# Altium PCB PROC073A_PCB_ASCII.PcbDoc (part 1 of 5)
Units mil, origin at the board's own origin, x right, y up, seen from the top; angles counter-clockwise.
Board outline 2165.35 x 2165.35 mil, 6 copper layers (Top Layer, L2, L3, L4, L5, Bottom Layer), stack 55.08 mil thick; 285 components, 233 nets, 945 pads, 1419 vias.
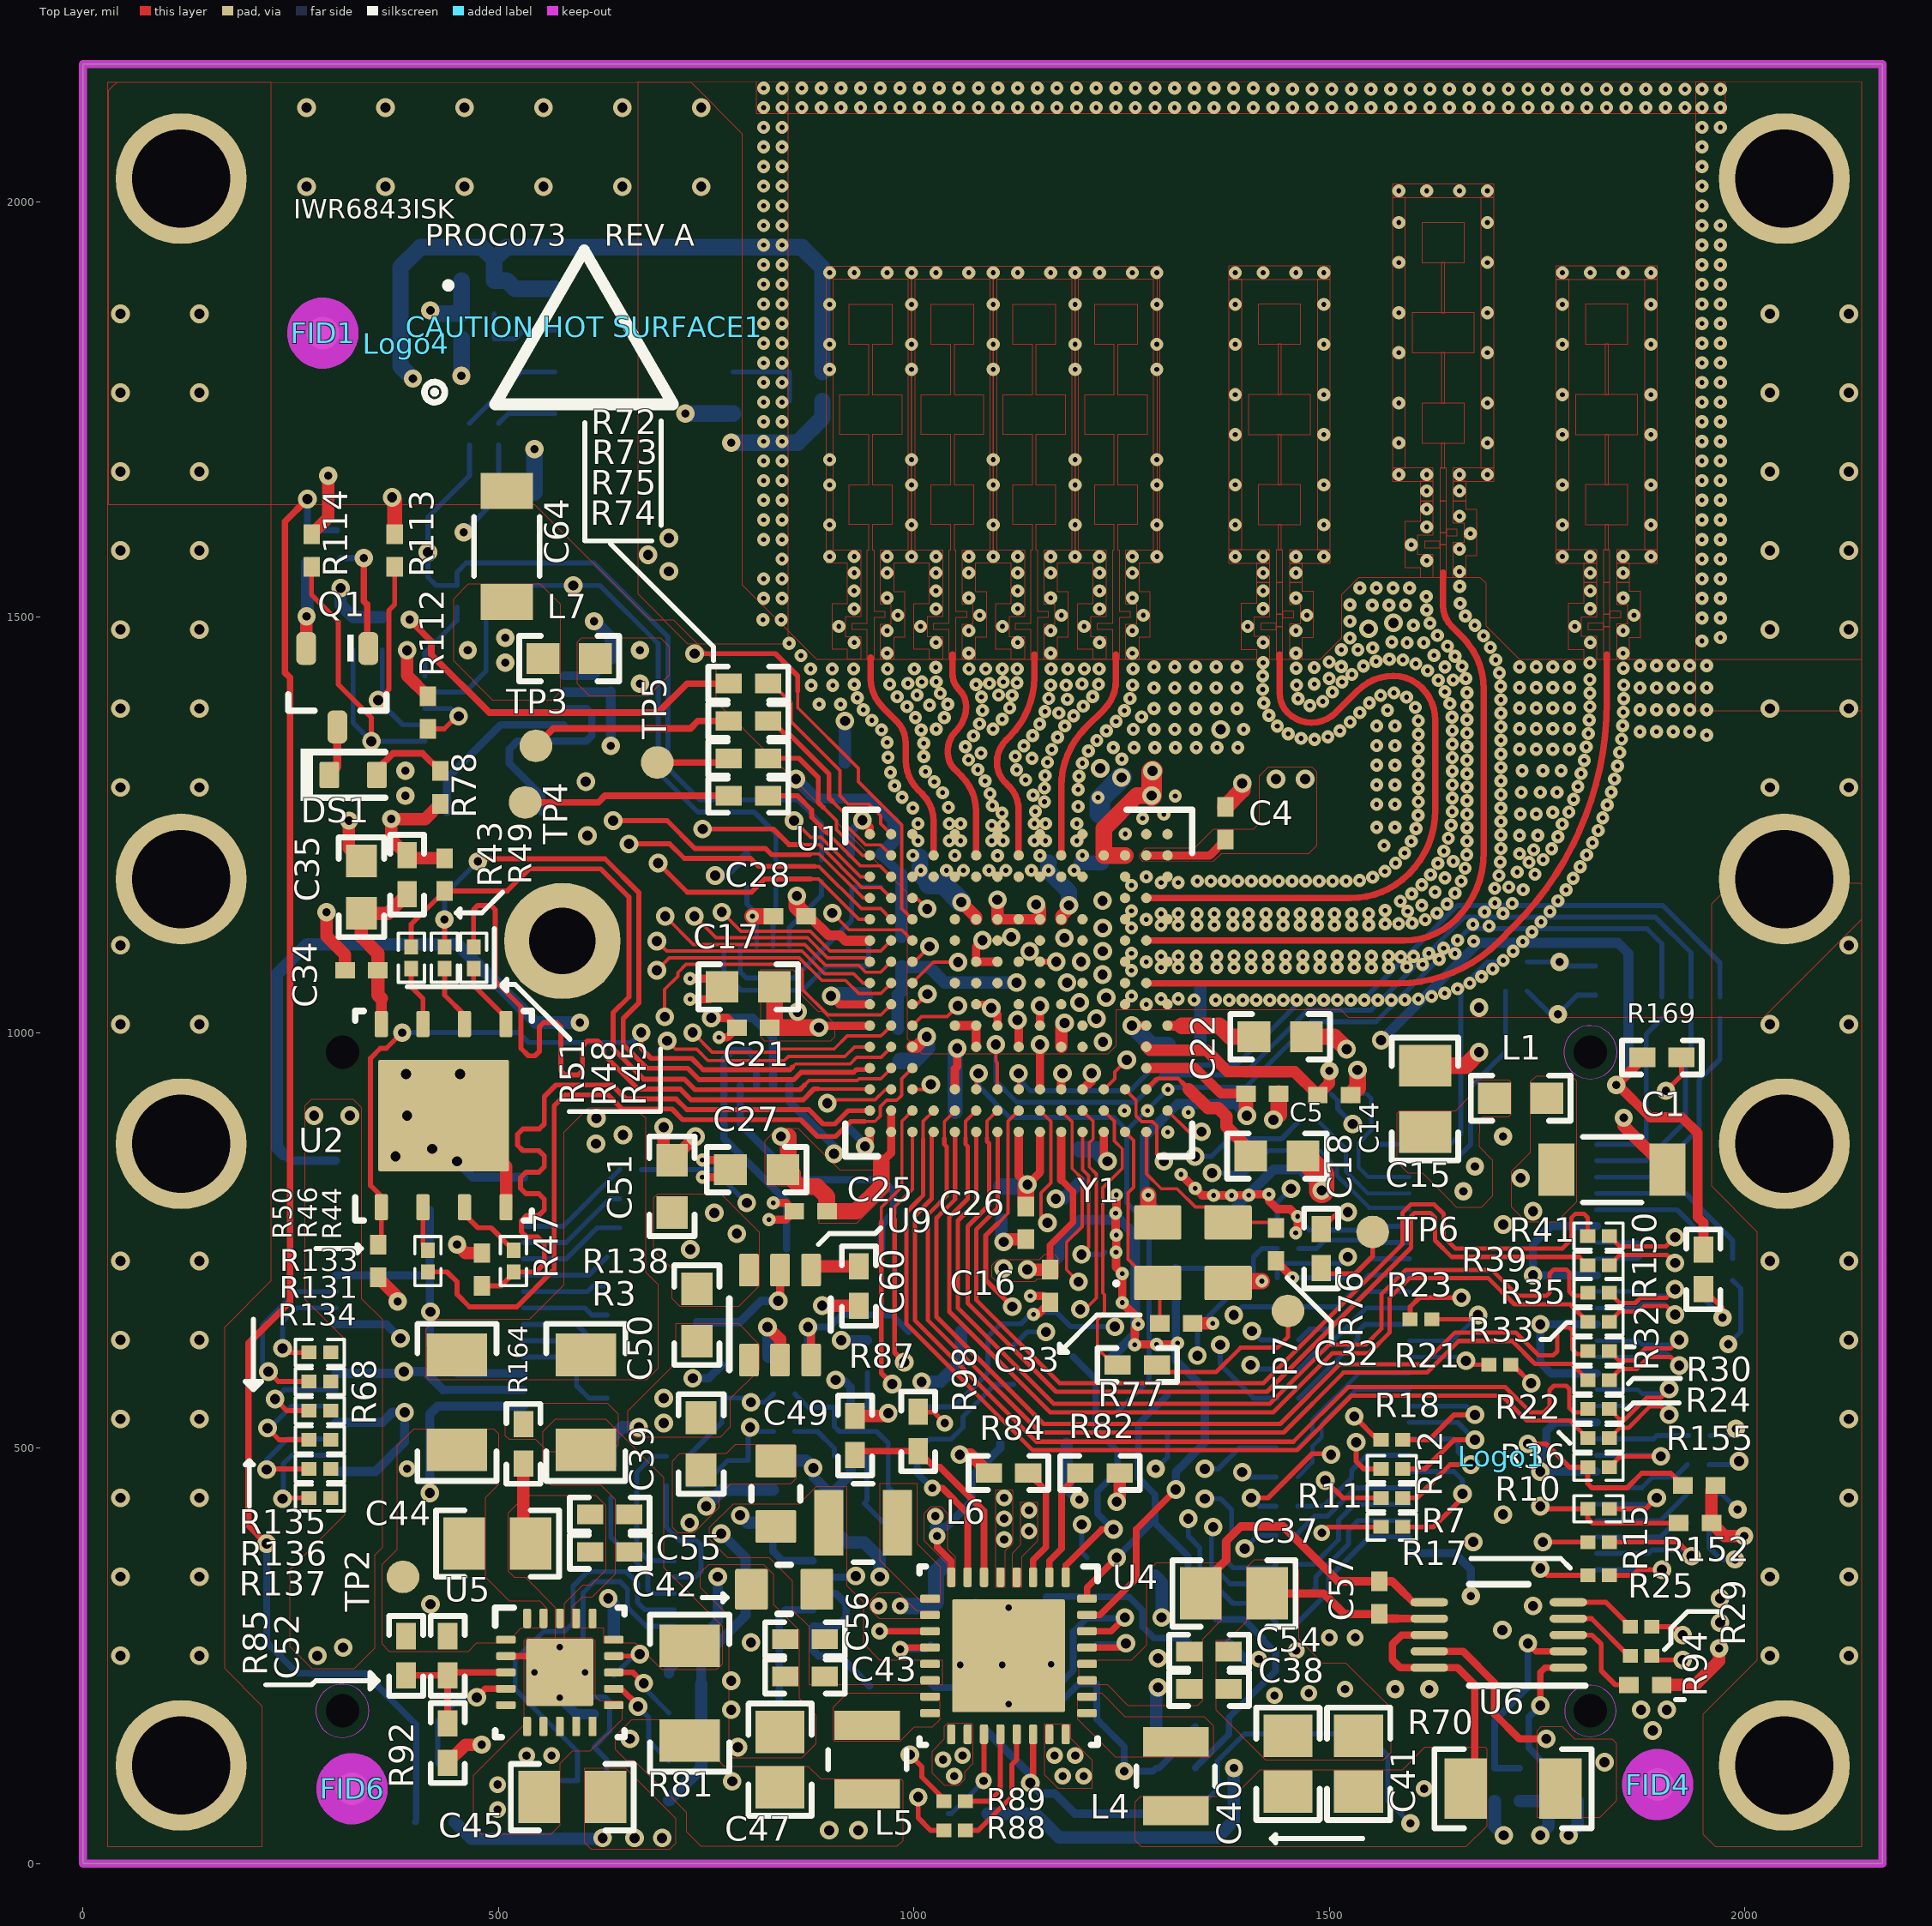
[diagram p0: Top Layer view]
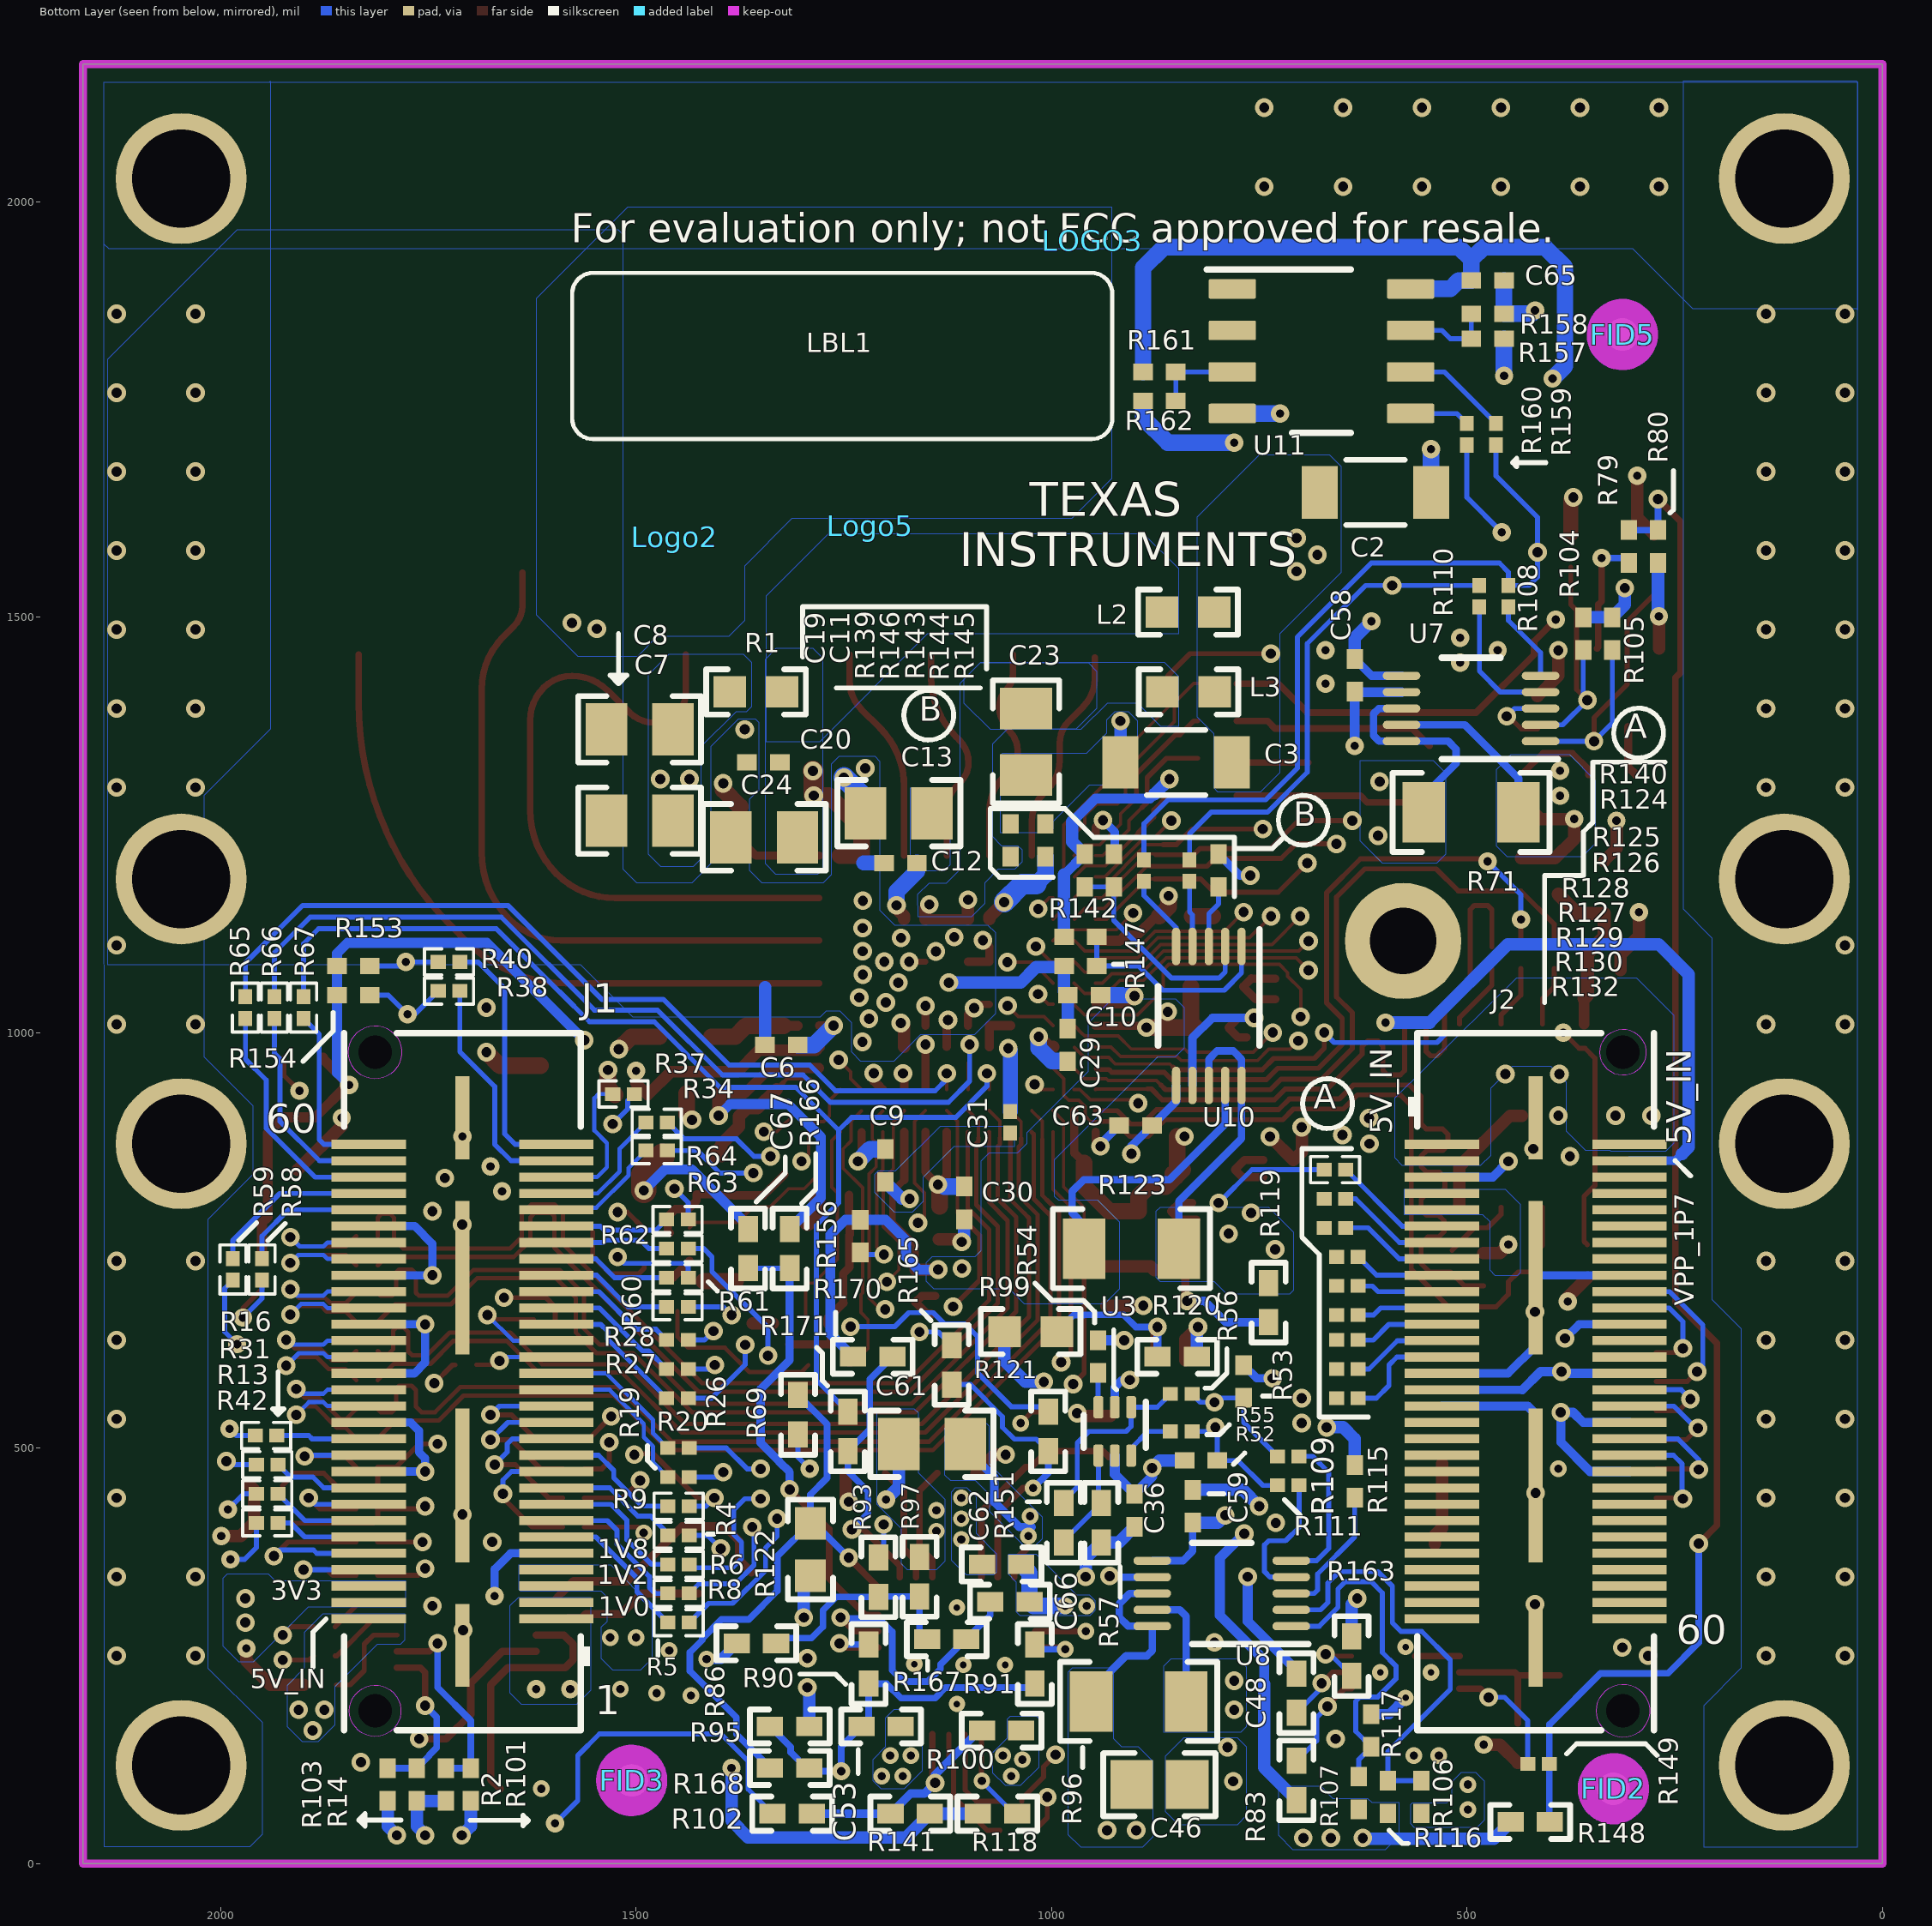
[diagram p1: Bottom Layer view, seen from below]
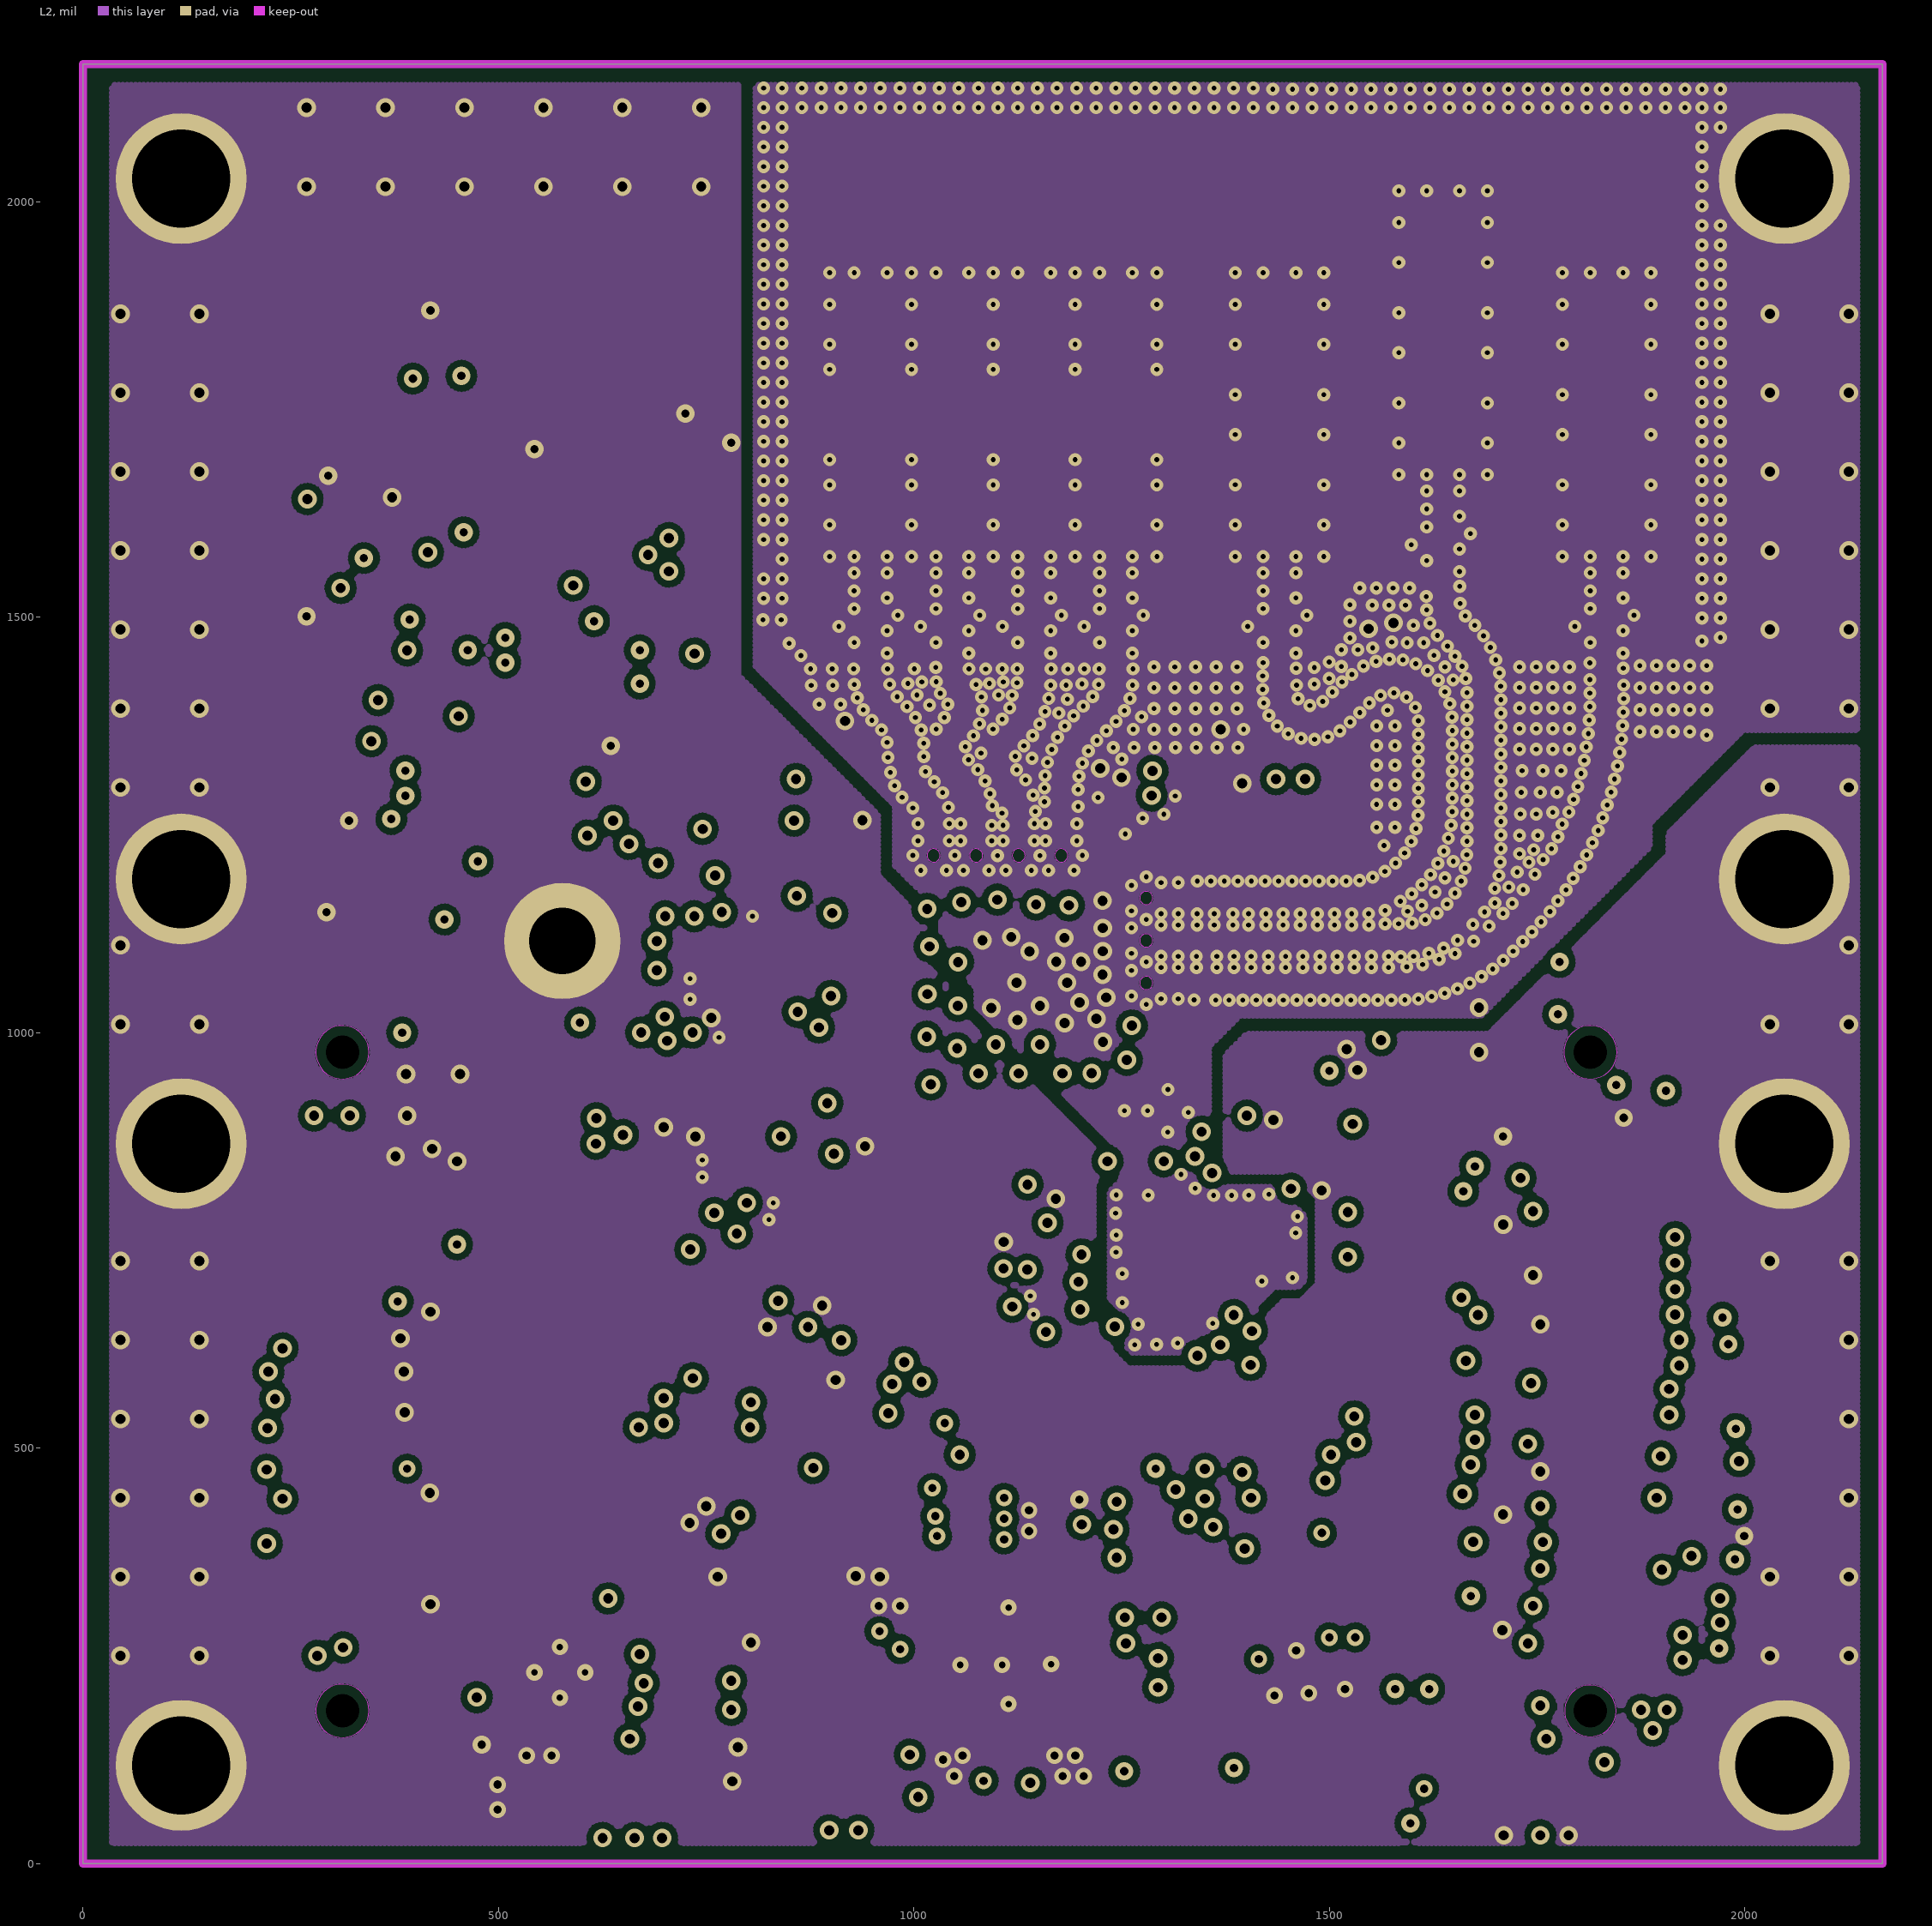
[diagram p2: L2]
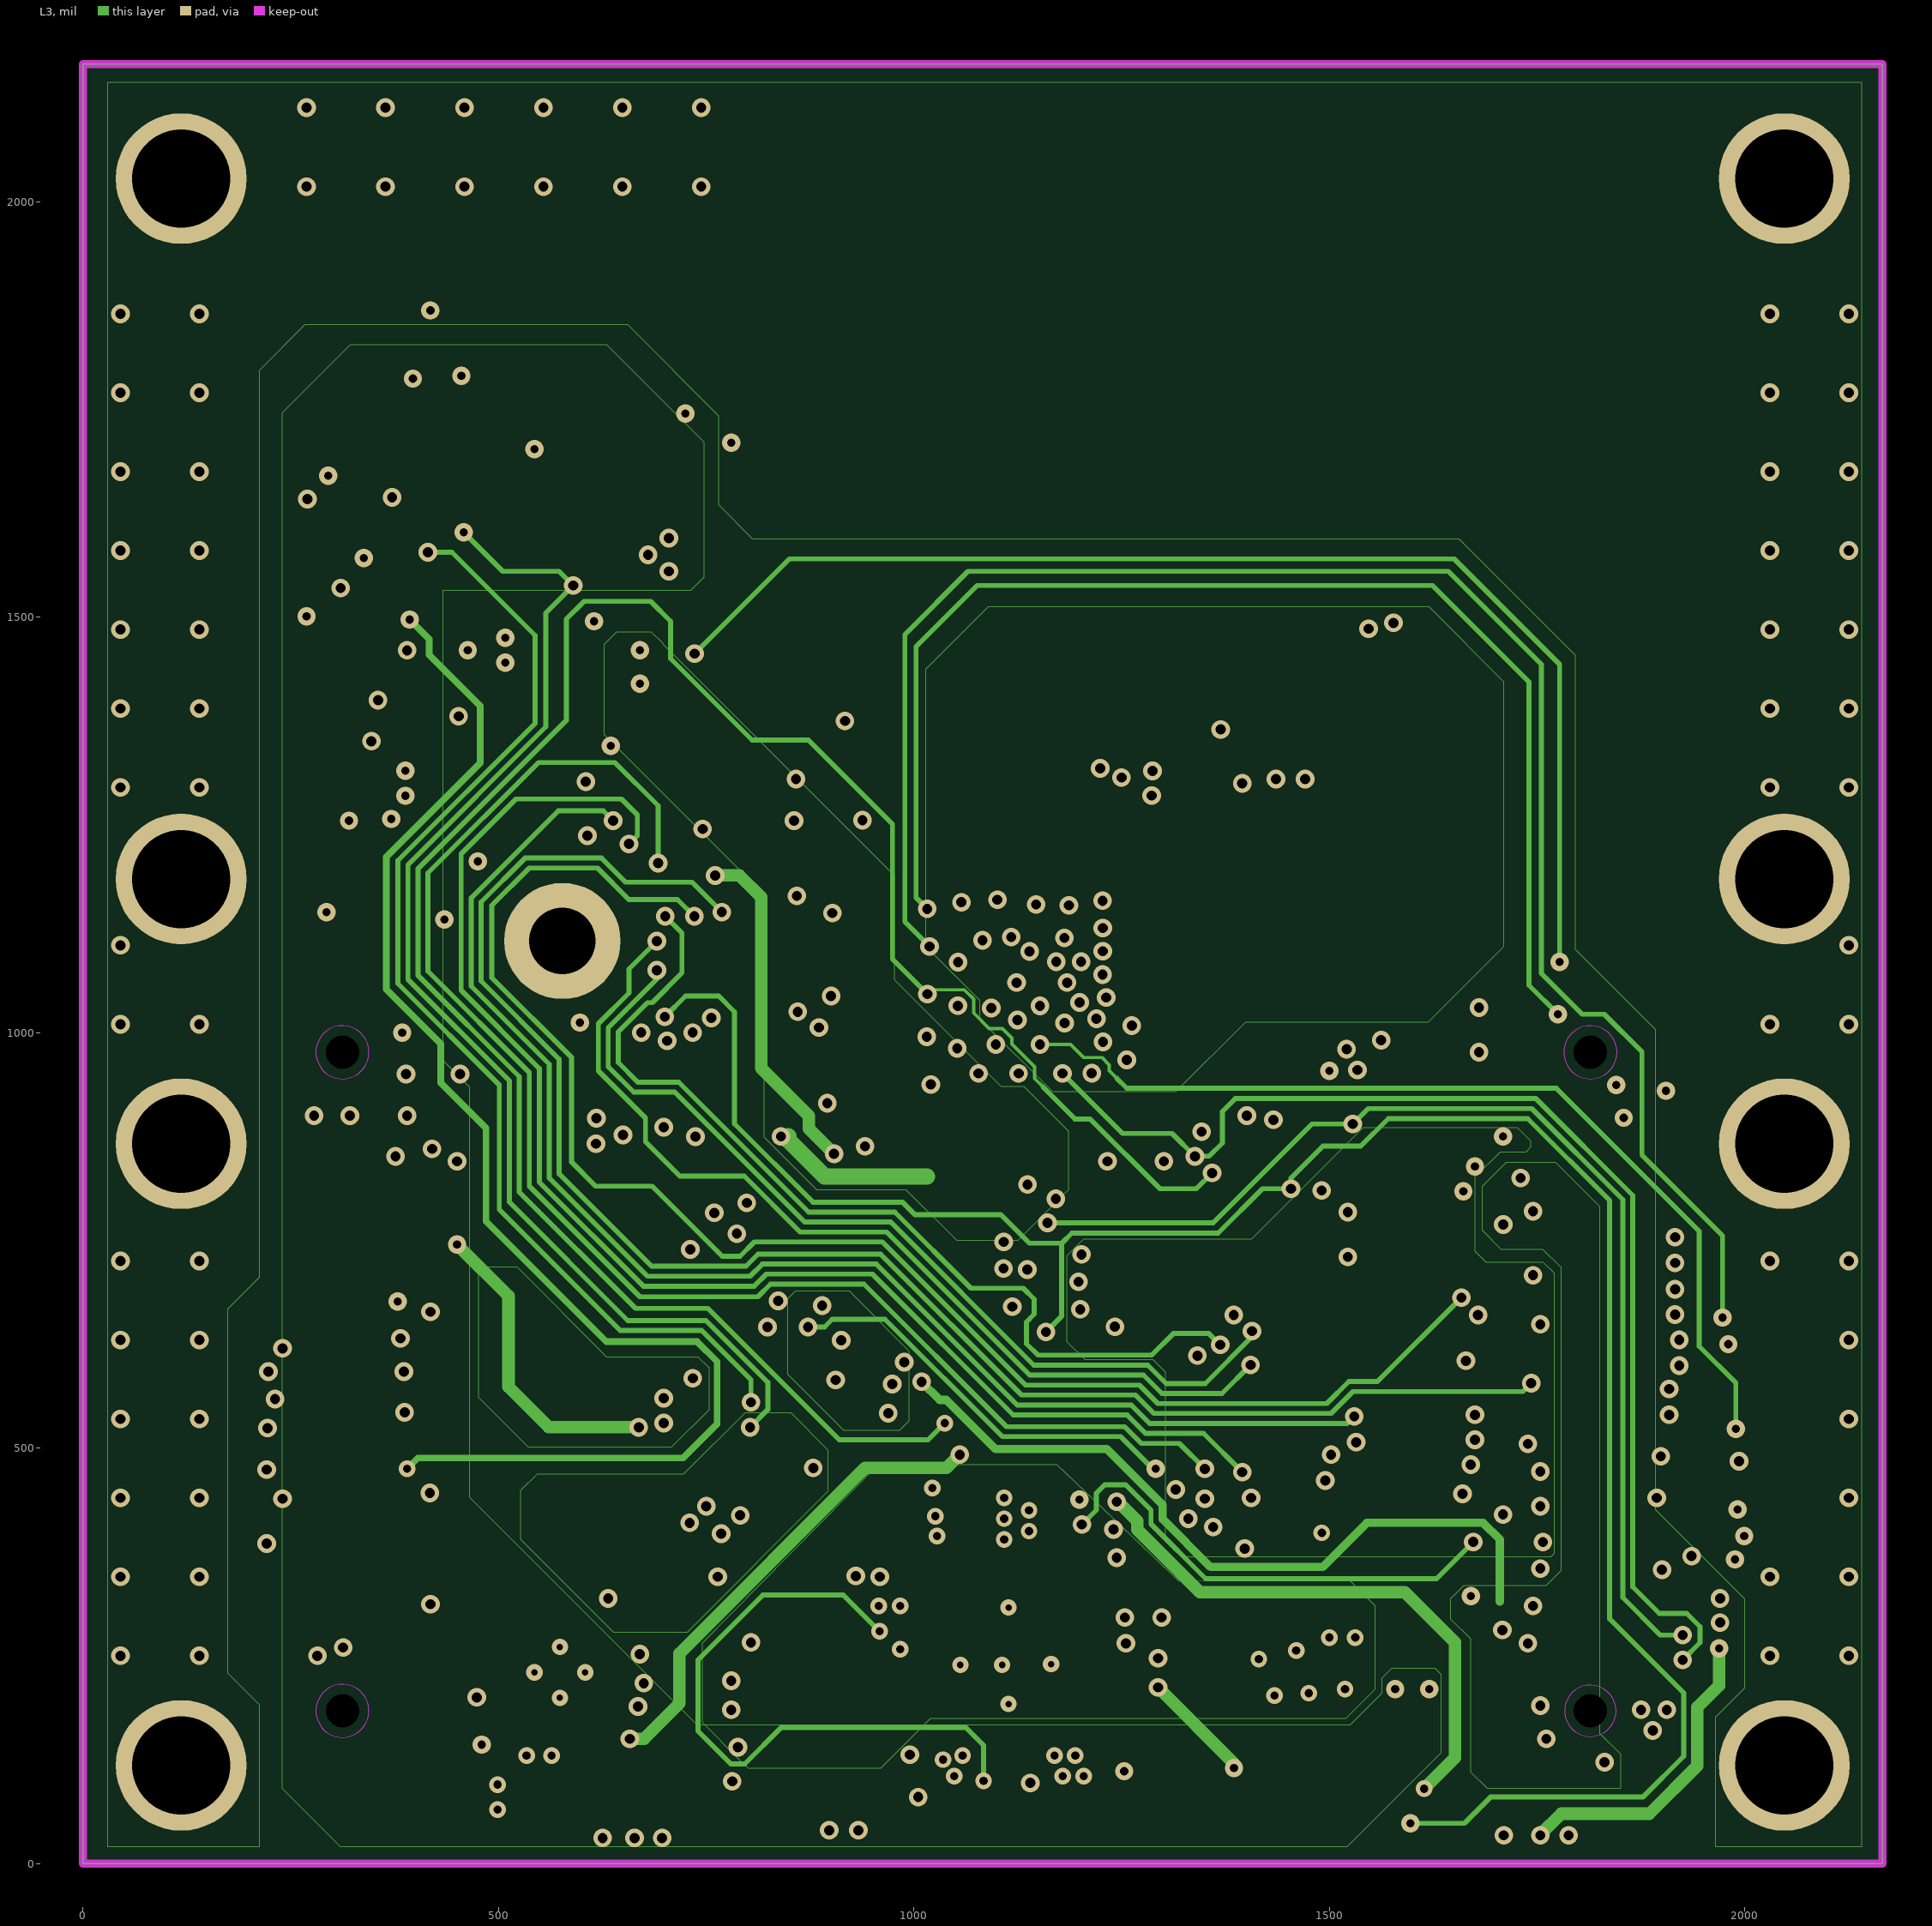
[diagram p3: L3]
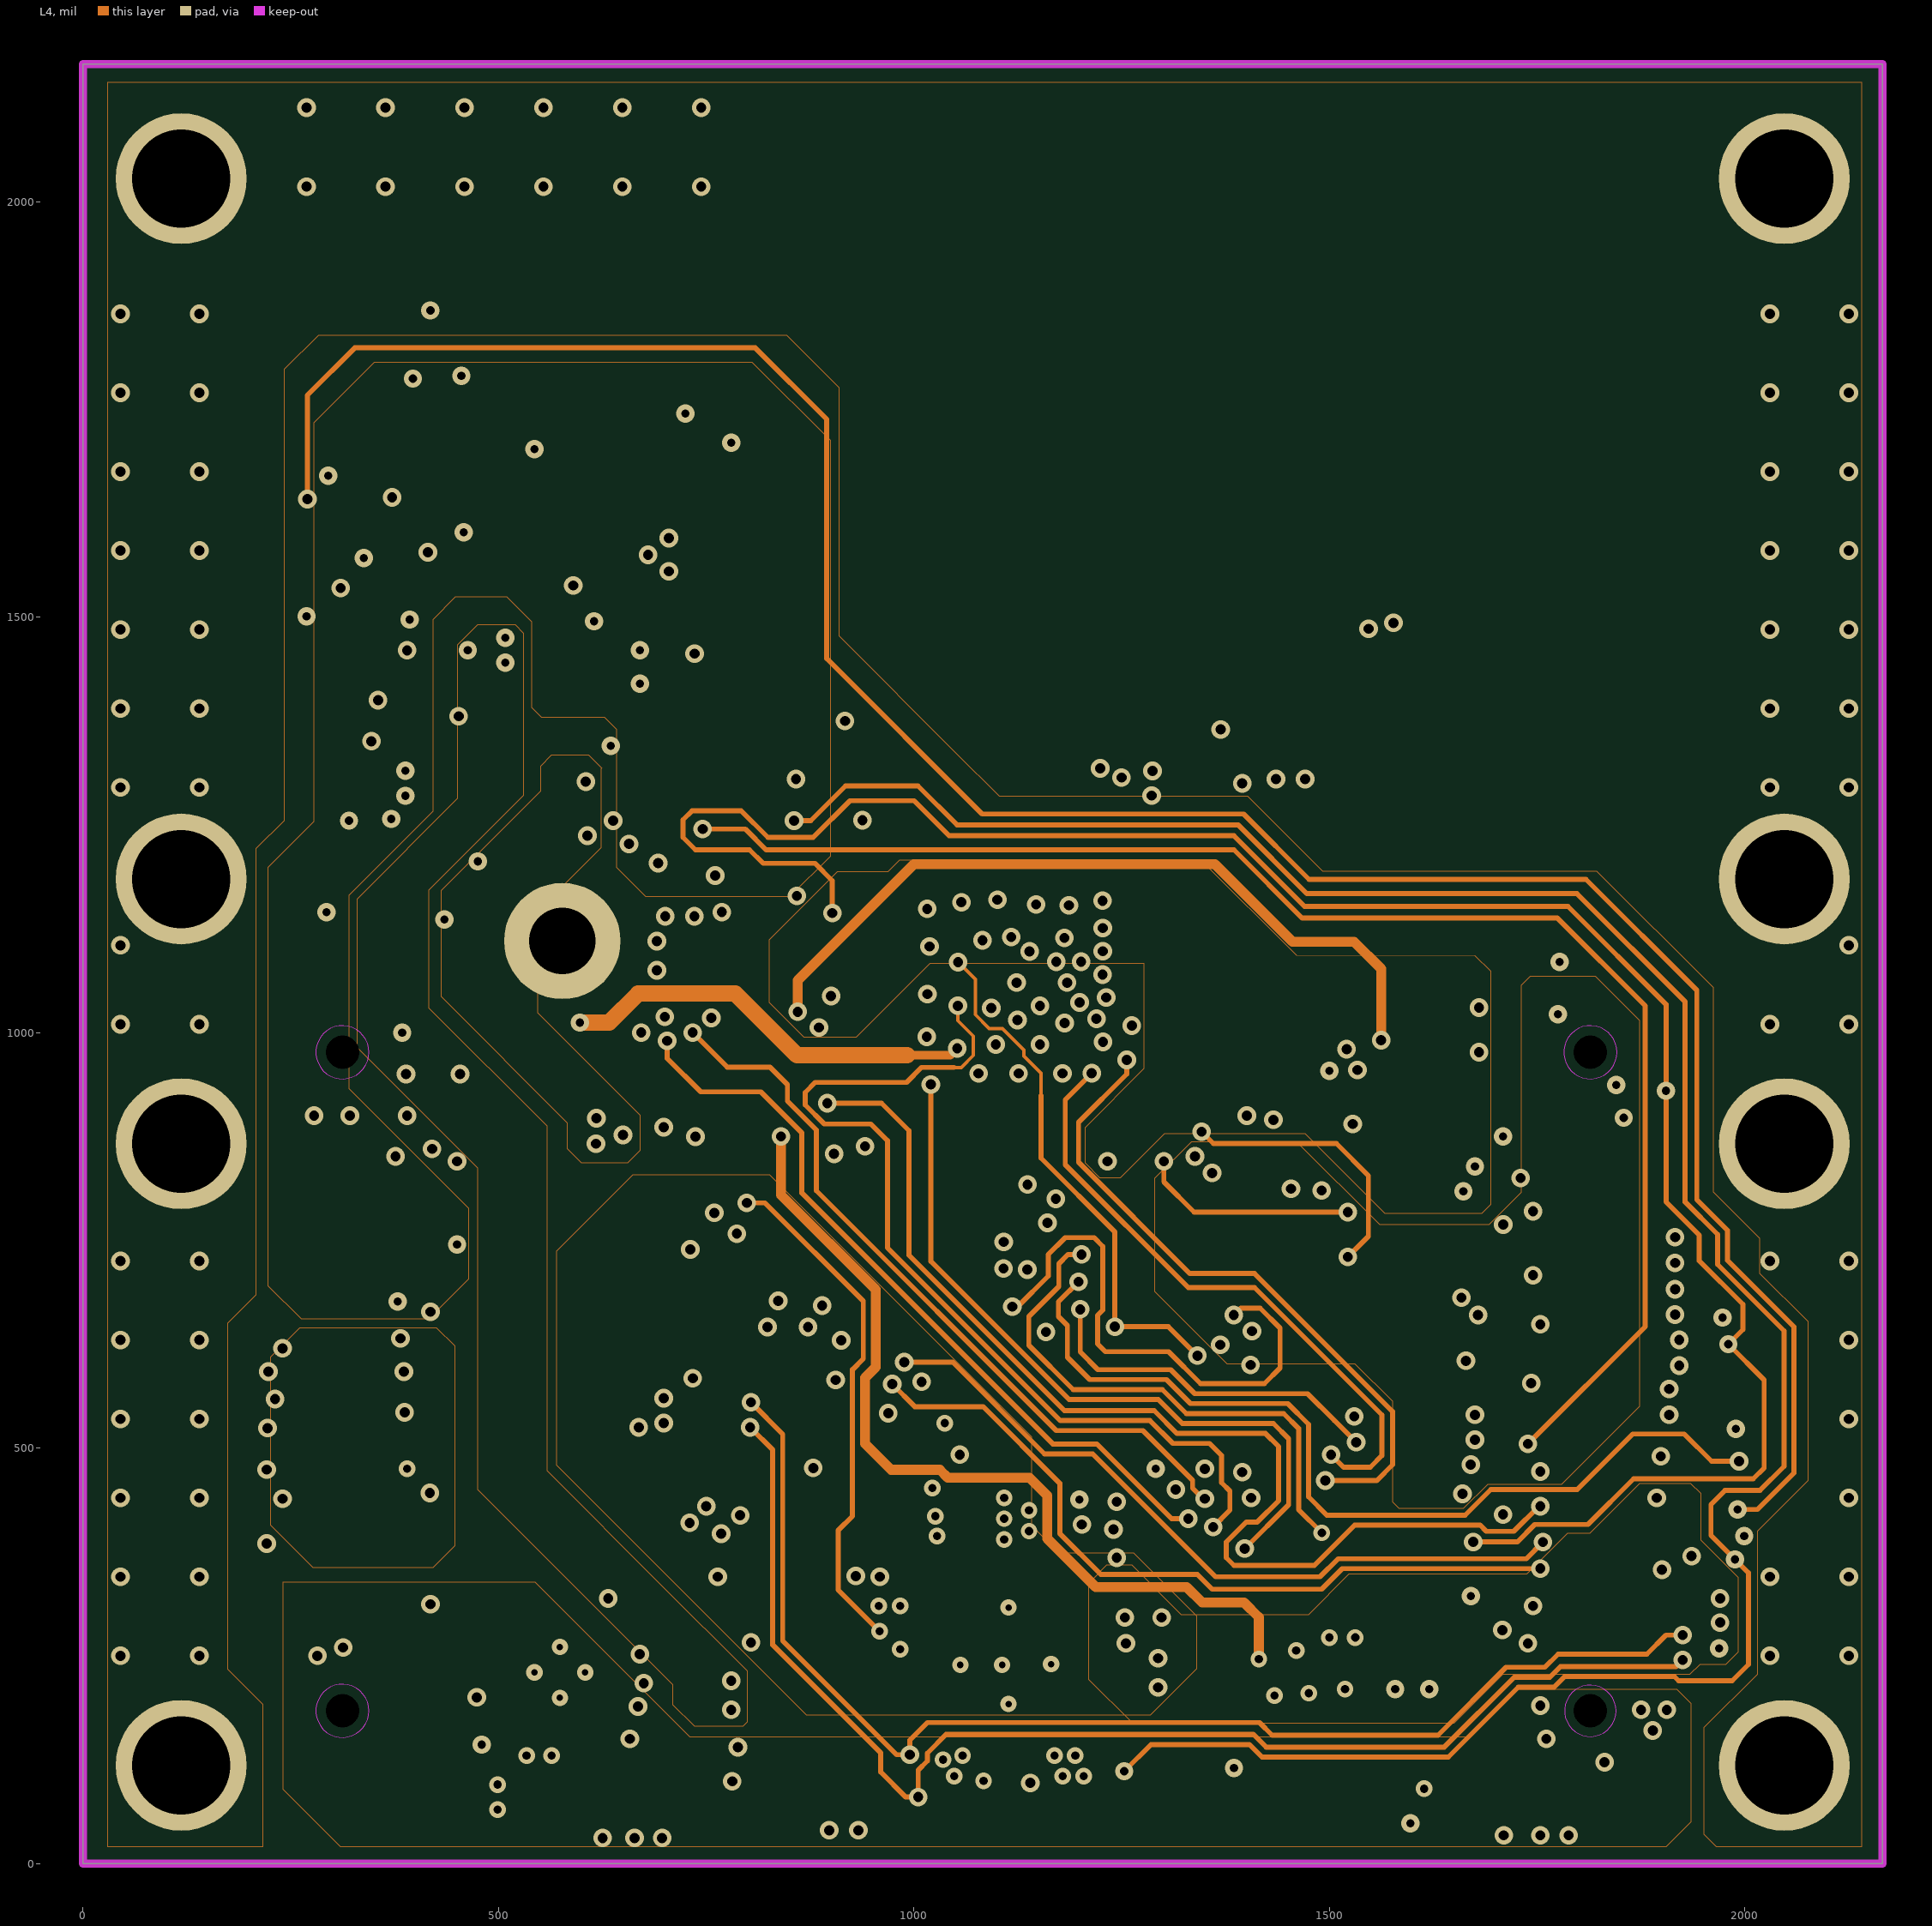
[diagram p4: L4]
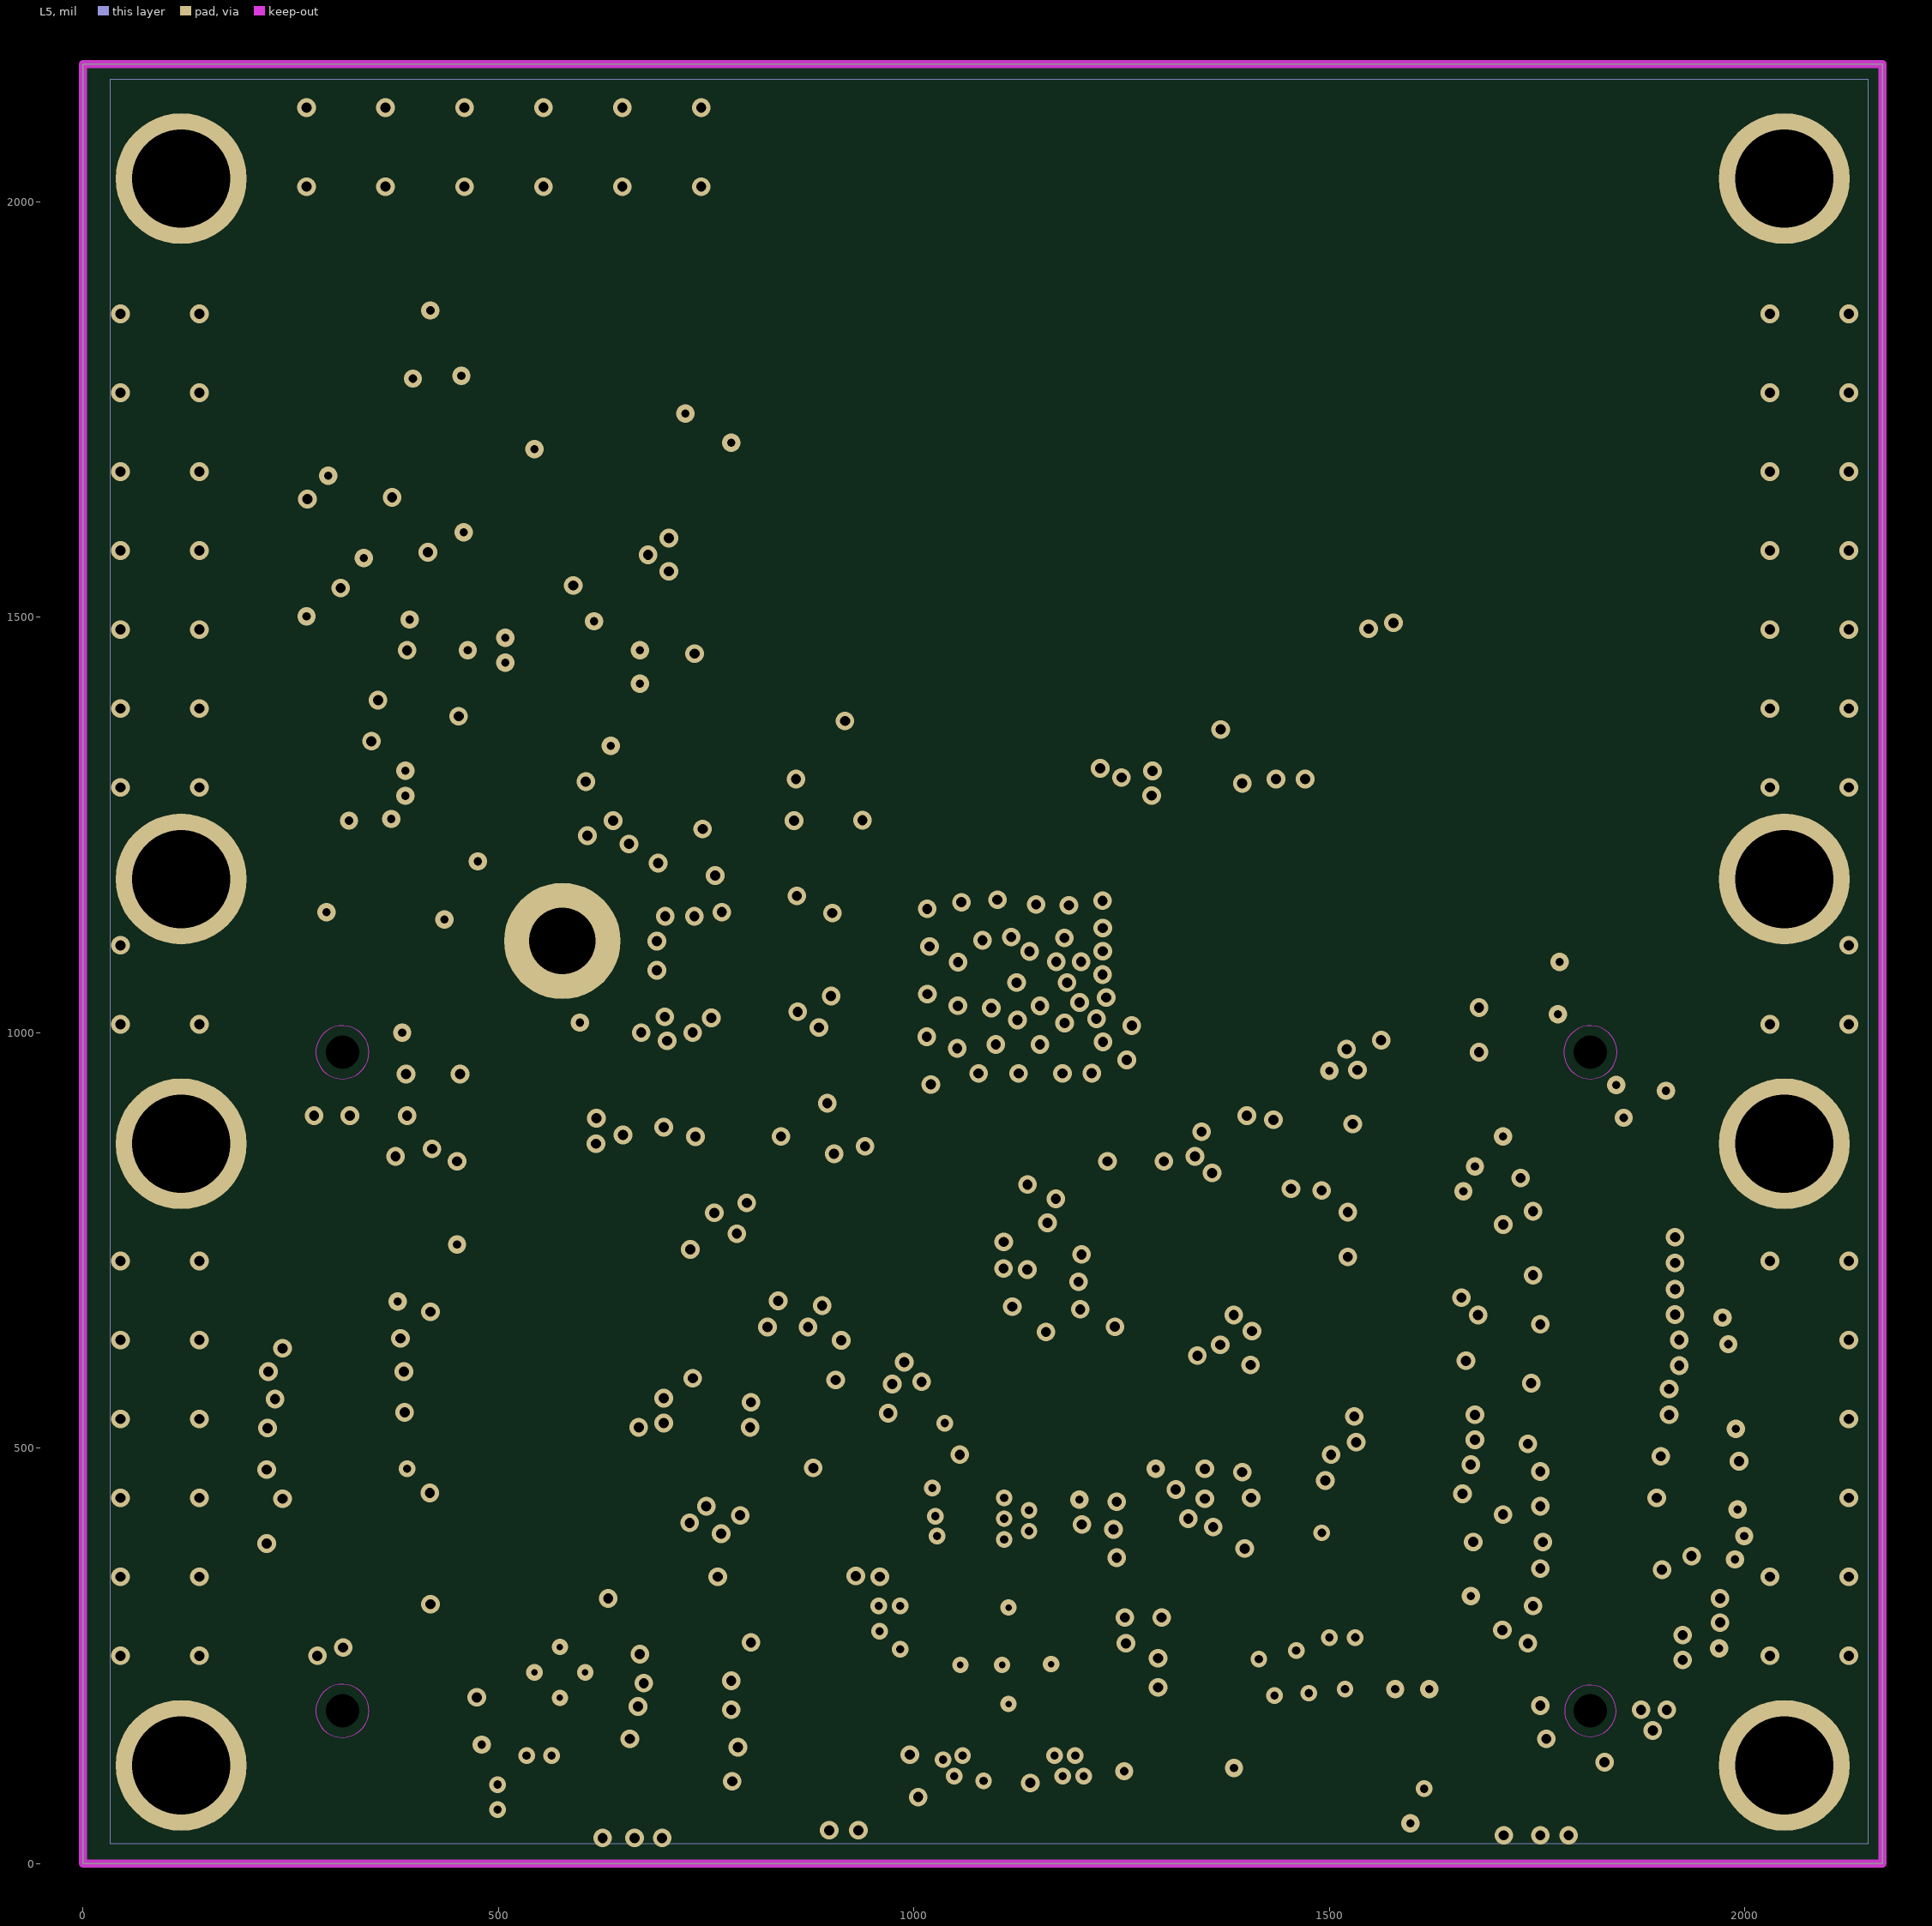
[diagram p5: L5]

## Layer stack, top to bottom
Top Solder: solder mask 0.8, Solder Resist, Dk 1
Top Layer: signal copper 1.6
Dielectric 1: dielectric 4, RO4835 LOPRO, Dk 3.66
L2: signal copper 1.2
Dielectric 2: dielectric 5.52, 1080 (66)X2  370HR, Dk 3.9
L3: signal copper 1.2
Dielectric 3: dielectric 28, 4-7628  370HR, Dk 4.36
L4: signal copper 1.2
Dielectric 4: dielectric 5.56, 1080 (66)X2  370HR, Dk 3.9
L5: signal copper 1.2
Dielectric 5: core 4, 1-2166   370HR, Dk 4.26
Bottom Layer: signal copper 1.6
Bottom Solder: solder mask 0.8, Solder Resist, Dk 1

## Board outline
0,0 2165.35,0 2165.35,2165.35 0,2165.35

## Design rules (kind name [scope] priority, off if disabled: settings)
AcuteAngle [All] p0: scope1count=1 scope1_0_kind=Board scope1_0_value=Board scope2count=1 scope2_0_kind=Board scope2_0_value=Board commentlength=0 minimum=4.50000000000000E+0001
AcuteAngle [All] p1: minimum=4.50000000000000E+0001 checktracksonly=FALSE
AssemblyTestPointUsage [All] p0: scope1count=1 scope1_0_kind=Board scope1_0_value=Board scope2count=1 scope2_0_kind=Board scope2_0_value=Board commentlength=0
AssemblyTestPointUsage [All] p1: valid=2
AssemblyTestpoint [All] p0: scope1count=1 scope1_0_kind=Board scope1_0_value=Board scope2count=1 scope2_0_kind=Board scope2_0_value=Board commentlength=0
Clearance "Clr_L2_GND Cut out (400 Mircrons)" [All] p0 off: scope1count=1 scope1_0_kind=Board scope1_0_value=Board scope2count=1 scope2_0_kind=Board scope2_0_value=Board commentlength=48 gap=0 // Protel DXP Scope 2 Expression Was: IsKeepOut
Clearance "Clr_L1_GND Cut Out (800 Mirons)_1" [All] p0: scope1count=1 scope1_0_kind=Layer scope1_0_value=MID1 scope2count=1 scope2_0_kind=Board scope2_0_value=Board commentlength=0 gap=6
Clearance "Clearance_Diff Pairs_LVDS" [All] p0: scope1count=1 scope1_0_kind=NetClass scope1_0_value="Diff Pairs" scope2count=1 scope2_0_kind=NetClass scope2_0_value="Diff Pairs" commentlength=0 gap=6
Clearance "Clr_L1_GND Cut Out (800 Mirons)" [All] p0 off: scope1count=1 scope1_0_kind=Board scope1_0_value=Board scope2count=1 scope2_0_kind=Board scope2_0_value=Board commentlength=48 gap=0 // Protel DXP Scope 2 Expression Was: IsKeepOut
Clearance "Clearance_TX and RX" [All] p0: scope1count=1 scope1_0_kind=NetClass scope1_0_value="TX and RX" scope2count=1 scope2_0_kind=Board scope2_0_value=Board commentlength=0 gap=8
Clearance Clearance_BGA [All] p0 off: scope1count=1 scope1_0_kind=Board scope1_0_value=Board scope2count=1 scope2_0_kind=Board scope2_0_value=Board commentlength=57 gap=4 // Protel DXP Scope 1 Expression Was: WithinRoom('BGA1')
Clearance [All] p0: scope1count=1 scope1_0_kind=Board scope1_0_value=Board scope2count=1 scope2_0_kind=Board scope2_0_value=Board commentlength=0 gap=6
Clearance Clearance_Fid [All] p0 off: scope1count=1 scope1_0_kind=Board scope1_0_value=Board scope2count=1 scope2_0_kind=Board scope2_0_value=Board commentlength=81 gap=0 // Protel DXP Scope 2 Expression Was: IsPad and InComponentClass('FiducialMark')
Clearance "Clr_L2_GND Cut out (400 Mircrons)" [OnLayer('L2') and InPolygon vs IsKeepOut] p1: gap=0 ignorepadtopadclearanceinfootprint=FALSE except(7: Arc-Arc Arc-Track)
Clearance "Clr_L1_GND Cut Out (800 Mirons)_1" [OnLayer('L2')] p2: gap=6 ignorepadtopadclearanceinfootprint=FALSE except(0: Arc-Hole Track-Hole SMDPad-Hole THPad-Hole Via-Hole Fill-Hole Poly-Hole Region-Hole Text-Hole; 8: Arc-Fill Arc-Poly Arc-Region Track-Fill Track-Poly Track-Region SMDPad-Fill SMDPad-Poly SMDPad-Region THPad-Fill THPad-Poly THPad-Region Via-Fill Via-Poly Via-Region Fill-Fill Fill-Poly Fill-Region Poly-Poly Poly-Region Region-Region)
Clearance Clearance_Fid [IsKeepOut and InComponentClass('FiducialMark') vs IsPad and InComponentClass('FiducialMark')] p3: gap=0 ignorepadtopadclearanceinfootprint=FALSE
Clearance "Clearance_Diff Pairs_LVDS" [InNetClass('Diff Pairs') vs InNetClass('Diff Pairs')] p4: gap=6 ignorepadtopadclearanceinfootprint=FALSE except(0: Arc-Hole Track-Hole SMDPad-Hole THPad-Hole Via-Hole Fill-Hole Poly-Hole Region-Hole Text-Hole; 4: Arc-SMDPad Arc-THPad Arc-Via Track-SMDPad Track-THPad Track-Via; 5: Arc-Arc Arc-Track Track-Track; 8: Arc-Fill Arc-Poly Arc-Region Track-Fill Track-Poly Track-Region Via-Fill Via-Poly Via-Region Fill-Fill Fill-Poly Fill-Region Poly-Poly Poly-Region Region-Region)
Clearance "Clr_L1_GND Cut Out (800 Mirons)" [OnTopLayer and InPoly vs IsKeepOut] p5: gap=0 ignorepadtopadclearanceinfootprint=FALSE
Clearance "Clearance_TX and RX" [InNetClass('TX and RX')] p6: gap=8 ignorepadtopadclearanceinfootprint=FALSE except(0: Arc-Hole Track-Hole SMDPad-Hole THPad-Hole Via-Hole Fill-Hole Poly-Hole Region-Hole Text-Hole; 4: Arc-Text Track-Text SMDPad-Text THPad-Text Via-Text Fill-Text Poly-Text Region-Text Text-Text; 7.7: Fill-Fill Fill-Poly Fill-Region Poly-Poly Poly-Region Region-Region; 7.9: Arc-Via Track-Via; 10: Arc-SMDPad Arc-THPad Track-SMDPad Track-THPad SMDPad-SMDPad SMDPad-THPad SMDPad-Via THPad-THPad THPad-Via)
Clearance Clearance_BGA [WithinRoom('BGA1')] p7: gap=4 ignorepadtopadclearanceinfootprint=FALSE except(0: Arc-Hole Track-Hole SMDPad-Hole THPad-Hole Via-Hole Fill-Hole Poly-Hole Region-Hole Text-Hole; 6: SMDPad-Poly THPad-Poly Via-Poly; 7.5: Region-Region; 7.87: Arc-Text Track-Text SMDPad-Text THPad-Text Via-Text Fill-Text Poly-Text Region-Text Text-Text; 8: Arc-Poly Track-THPad Track-Poly THPad-THPad Fill-Poly Poly-Poly)
Clearance [All] p8: gap=6 ignorepadtopadclearanceinfootprint=FALSE except(0: Arc-Hole Track-Hole SMDPad-Hole THPad-Hole Via-Hole Fill-Hole Poly-Hole Region-Hole Text-Hole; 8: Arc-Fill Arc-Poly Arc-Region Track-Fill Track-Poly Track-Region SMDPad-Fill SMDPad-Poly SMDPad-Region THPad-Fill THPad-Poly THPad-Region Via-Fill Via-Poly Via-Region Fill-Fill Fill-Poly Fill-Region Poly-Poly Poly-Region Region-Region)
ComponentClearance "ComponentClearance_WEE Logo" [All] p0: scope1count=1 scope1_0_kind=Component scope1_0_value=Logo4 scope2count=1 scope2_0_kind=Board scope2_0_value=Board commentlength=0 gap=0 collisioncheckmode=3
ComponentClearance Comp_Clr-R158_R157 [All] p0: scope1count=1 scope1_0_kind=Component scope1_0_value=R157 scope2count=1 scope2_0_kind=Component scope2_0_value=R158 commentlength=0 gap=0 collisioncheckmode=3
ComponentClearance Comp_Clr-R101_R2 [All] p0: scope1count=1 scope1_0_kind=Component scope1_0_value=R2 scope2count=1 scope2_0_kind=Component scope2_0_value=R101 commentlength=0 gap=0 collisioncheckmode=3
ComponentClearance Comp_Clr-C42_L6 [All] p0: scope1count=1 scope1_0_kind=Component scope1_0_value=C42 scope2count=1 scope2_0_kind=Component scope2_0_value=L6 commentlength=0 gap=0 collisioncheckmode=3
ComponentClearance ComponentClearance_R77 [All] p0: scope1count=1 scope1_0_kind=Component scope1_0_value=R77 scope2count=1 scope2_0_kind=Component scope2_0_value=Logo1 commentlength=0 gap=0 collisioncheckmode=3
ComponentClearance ComponentClearance_Logo [All] p0: scope1count=1 scope1_0_kind=ComponentClass scope1_0_value=Logo scope2count=1 scope2_0_kind=Board scope2_0_value=Board commentlength=0 gap=0 collisioncheckmode=3
ComponentClearance "ComponentClearance_Mounting Holes_Fiducial Marks" [All] p0: scope1count=1 scope1_0_kind=ComponentClass scope1_0_value=FiducialMark scope2count=1 scope2_0_kind=PadClass scope2_0_value="Mounting Holes PADS" commentlength=0 gap=50 collisioncheckmode=3
ComponentClearance [All] p0: scope1count=1 scope1_0_kind=Board scope1_0_value=Board scope2count=1 scope2_0_kind=Board scope2_0_value=Board commentlength=0 gap=10 collisioncheckmode=3
ComponentClearance "ComponentClearance_WEE Logo" [InComponent('Logo4')] p1: gap=0 collisioncheckmode=3 verticalgap=0 showdistances=TRUE
ComponentClearance Comp_Clr-R158_R157 [InComponent('R157') vs InComponent('R158')] p2: gap=0 collisioncheckmode=3 verticalgap=0 showdistances=TRUE
ComponentClearance Comp_Clr-R101_R2 [InComponent('R2') vs InComponent('R101')] p3: gap=0 collisioncheckmode=3 verticalgap=0 showdistances=TRUE
ComponentClearance Comp_Clr-C42_L6 [InComponent('C42') vs InComponent('L6')] p4: gap=0 collisioncheckmode=3 verticalgap=0 showdistances=TRUE
ComponentClearance ComponentClearance_R77 [InComponent('R77') vs InComponent('Logo1')] p5: gap=0 collisioncheckmode=3 verticalgap=0 showdistances=TRUE
ComponentClearance ComponentClearance_Logo [InComponentClass('Logo')] p6: gap=0 collisioncheckmode=3 verticalgap=0 showdistances=TRUE
ComponentClearance "ComponentClearance_Mounting Holes_Fiducial Marks" [InComponentClass('FiducialMark') vs InPadClass('Mounting Holes PADS')] p7: gap=50 collisioncheckmode=3 verticalgap=10 showdistances=TRUE
ComponentClearance [All] p8: gap=10 collisioncheckmode=3 verticalgap=10 showdistances=TRUE
DiffPairsRouting [All] p0: scope1count=1 scope1_0_kind=Board scope1_0_value=Board scope2count=1 scope2_0_kind=Board scope2_0_value=Board commentlength=0
DiffPairsRouting [All] p1: maxlimit=5 minlimit=4 mostfreqgap=5 toplayer_minwidth=4 toplayer_maxwidth=5.2 toplayer_prefwidth=5.2 midlayer1_minwidth=4 midlayer1_maxwidth=5.2 midlayer1_prefwidth=5.2 midlayer2_minwidth=4 midlayer2_maxwidth=5.2 midlayer2_prefwidth=5.2 midlayer3_minwidth=4 midlayer3_maxwidth=5.2 midlayer3_prefwidth=5.2 midlayer4_minwidth=4 midlayer4_maxwidth=5.2 midlayer4_prefwidth=5.2 bottomlayer_minwidth=4 bottomlayer_maxwidth=5.2 bottomlayer_prefwidth=5.2 maxuncoupledlength=500
FabricationTestPointUsage TestPointUsage [All] p0: scope1count=1 scope1_0_kind=Board scope1_0_value=Board scope2count=1 scope2_0_kind=Board scope2_0_value=Board commentlength=0 valid=2 allowmultiple=FALSE
FabricationTestPointUsage TestPointUsage [All] p1: valid=2 allowmultiple=FALSE
FabricationTestpoint Testpoint [All] p0: scope1count=1 scope1_0_kind=Board scope1_0_value=Board scope2count=1 scope2_0_kind=Board scope2_0_value=Board commentlength=0 side=3 testpointundercomponent=TRUE minsize=40 maxsize=100 preferedsize=60 minholesize=0 maxholesize=40 preferedholesize=32 testpointgrid=1
FabricationTestpoint Testpoint [All] p1: side=3 testpointundercomponent=TRUE minsize=40 maxsize=100 preferedsize=60 minholesize=0 maxholesize=40 preferedholesize=32 testpointgrid=1 allowsidetop=TRUE allowsidebottom=TRUE usegrid=TRUE gridtolerance=0.01
FanoutControl Fanout_LCC [All] p0 off: scope1count=1 scope1_0_kind=Board scope1_0_value=Board scope2count=1 scope2_0_kind=Board scope2_0_value=Board commentlength=69 // Protel DXP Scope 1 Expression Was: IsLCC   Fanout_LCC (Default Rule)
FanoutControl Fanout_BGA [All] p0 off: scope1count=1 scope1_0_kind=Board scope1_0_value=Board scope2count=1 scope2_0_kind=Board scope2_0_value=Board commentlength=69 // Protel DXP Scope 1 Expression Was: IsBGA   Fanout_BGA (Default Rule)
FanoutControl Fanout_SOIC [All] p0 off: scope1count=1 scope1_0_kind=Board scope1_0_value=Board scope2count=1 scope2_0_kind=Board scope2_0_value=Board commentlength=71 // Protel DXP Scope 1 Expression Was: IsSOIC   Fanout_SOIC (Default Rule)
FanoutControl Fanout_Default [All] p0: scope1count=1 scope1_0_kind=Board scope1_0_value=Board scope2count=1 scope2_0_kind=Board scope2_0_value=Board commentlength=30 // Fanout_Default (Default Rule)
FanoutControl Fanout_Small [All] p0 off: scope1count=1 scope1_0_kind=Board scope1_0_value=Board scope2count=1 scope2_0_kind=Board scope2_0_value=Board commentlength=84 // Protel DXP Scope 1 Expression Was: (CompPinCount < 5)   Fanout_Small (Default Rule)
FanoutControl Fanout_LCC [IsLCC] p1: bgadir=Out bgaviamode=Centered fanoutstyle=Auto fanoutdirection=Alternating viagrid=1 // Fanout_LCC (Default Rule)
FanoutControl Fanout_BGA [IsBGA] p2: bgadir=Out bgaviamode=Centered fanoutstyle=Auto fanoutdirection=Alternating viagrid=1 // Fanout_BGA (Default Rule)
FanoutControl Fanout_Default [All] p4: bgadir=Out bgaviamode=Centered fanoutstyle=Auto fanoutdirection=Alternating viagrid=1 // Fanout_Default (Default Rule)
FanoutControl Fanout_Small [(CompPinCount < 5)] p5: bgadir=Out bgaviamode=Centered fanoutstyle=Auto fanoutdirection=OutThenIn viagrid=1 // Fanout_Small (Default Rule)
Height Room_Hieght [All] p0 off: scope1count=1 scope1_0_kind=Board scope1_0_value=Board scope2count=1 scope2_0_kind=Board scope2_0_value=Board commentlength=69 // Protel DXP Scope 1 Expression Was: WithinRoom('Room_Hieght 1 MM')
Height Room_Hieght [WithinRoom('Room_Hieght 1 MM')] p1: minheight=0 maxheight=41.34 prefheight=39.37
HoleSize [All] p0: scope1count=1 scope1_0_kind=Board scope1_0_value=Board scope2count=1 scope2_0_kind=Board scope2_0_value=Board commentlength=0 absolutevalues=TRUE maxlimit=280 minlimit=5.9 maxpercent=80.000 minpercent=20.000
HoleSize [All] p1: absolutevalues=TRUE maxlimit=280 minlimit=5.9 maxpercent=80.000 minpercent=20.000
HoleToHoleClearance HoleToHoleClearance_1 [All] p0 off: scope1count=1 scope1_0_kind=Board scope1_0_value=Board scope2count=1 scope2_0_kind=Board scope2_0_value=Board commentlength=73 // Protel DXP Scope 2 Expression Was: InDrillLayerPair('Top Layer - L2')
HoleToHoleClearance [All] p0: scope1count=1 scope1_0_kind=Board scope1_0_value=Board scope2count=1 scope2_0_kind=Board scope2_0_value=Board commentlength=0
HoleToHoleClearance HoleToHoleClearance_1 [InDrillLayerPair('Top Layer - L2') vs InDrillLayerPair('Top Layer - L2')] p1: gap=7.7 allowstackedmicrovias=TRUE
HoleToHoleClearance [All] p2: gap=8 allowstackedmicrovias=TRUE
LayerPairs [All] p0: scope1count=1 scope1_0_kind=Board scope1_0_value=Board scope2count=1 scope2_0_kind=Board scope2_0_value=Board commentlength=0 enforce=TRUE
Length Length_Flash [All] p0: scope1count=1 scope1_0_kind=NetClass scope1_0_value=Flash scope2count=1 scope2_0_kind=Board scope2_0_value=Board commentlength=0 maxlimit=1026 minlimit=826
Length Length_Flash [InNetClass('Flash')] p1: maxlimit=1026 minlimit=826
MatchedLengths DiffPair_MatchedLengths [All] p0 off: scope1count=1 scope1_0_kind=Board scope1_0_value=Board scope2count=1 scope2_0_kind=Board scope2_0_value=Board commentlength=82 tolerance=5 amplitude=200 gap=20 style=90-Degree // Protel DXP Scope 1 Expression Was: InDifferentialPair ('NewDifferentialPair3')
MatchedLengths DiffPair_MatchedLengths_1 [All] p0 off: scope1count=1 scope1_0_kind=Board scope1_0_value=Board scope2count=1 scope2_0_kind=Board scope2_0_value=Board commentlength=82 tolerance=5 amplitude=200 gap=20 style=90-Degree // Protel DXP Scope 1 Expression Was: InDifferentialPair ('NewDifferentialPair2')
MatchedLengths DiffPair_MatchedLengths_2 [All] p0 off: scope1count=1 scope1_0_kind=Board scope1_0_value=Board scope2count=1 scope2_0_kind=Board scope2_0_value=Board commentlength=82 tolerance=5 amplitude=200 gap=20 style=90-Degree // Protel DXP Scope 1 Expression Was: InDifferentialPair ('NewDifferentialPair1')
MatchedLengths DiffPair_MatchedLengths_3 [All] p0 off: scope1count=1 scope1_0_kind=Board scope1_0_value=Board scope2count=1 scope2_0_kind=Board scope2_0_value=Board commentlength=82 tolerance=5 amplitude=200 gap=20 style=90-Degree // Protel DXP Scope 1 Expression Was: InDifferentialPair ('NewDifferentialPair8')
MatchedLengths DiffPair_MatchedLengths_4 [All] p0 off: scope1count=1 scope1_0_kind=Board scope1_0_value=Board scope2count=1 scope2_0_kind=Board scope2_0_value=Board commentlength=82 tolerance=5 amplitude=200 gap=20 style=90-Degree // Protel DXP Scope 1 Expression Was: InDifferentialPair ('NewDifferentialPair7')
MatchedLengths DiffPair_MatchedLengths_5 [All] p0 off: scope1count=1 scope1_0_kind=Board scope1_0_value=Board scope2count=1 scope2_0_kind=Board scope2_0_value=Board commentlength=82 tolerance=5 amplitude=200 gap=20 style=90-Degree // Protel DXP Scope 1 Expression Was: InDifferentialPair ('NewDifferentialPair6')
MatchedLengths DiffPair_MatchedLengths_6 [All] p0 off: scope1count=1 scope1_0_kind=Board scope1_0_value=Board scope2count=1 scope2_0_kind=Board scope2_0_value=Board commentlength=82 tolerance=5 amplitude=200 gap=20 style=90-Degree // Protel DXP Scope 1 Expression Was: InDifferentialPair ('NewDifferentialPair5')
MatchedLengths DiffPair_MatchedLengths_7 [All] p0 off: scope1count=1 scope1_0_kind=Board scope1_0_value=Board scope2count=1 scope2_0_kind=Board scope2_0_value=Board commentlength=82 tolerance=5 amplitude=200 gap=20 style=90-Degree // Protel DXP Scope 1 Expression Was: InDifferentialPair ('NewDifferentialPair3')
MatchedLengths DiffPair_MatchedLengths_8 [All] p0 off: scope1count=1 scope1_0_kind=Board scope1_0_value=Board scope2count=1 scope2_0_kind=Board scope2_0_value=Board commentlength=82 tolerance=5 amplitude=200 gap=20 style=90-Degree // Protel DXP Scope 1 Expression Was: InDifferentialPair ('NewDifferentialPair4')
MatchedLengths DiffPair_MatchedLengths_9 [All] p0 off: scope1count=1 scope1_0_kind=Board scope1_0_value=Board scope2count=1 scope2_0_kind=Board scope2_0_value=Board commentlength=82 tolerance=5 amplitude=200 gap=20 style=90-Degree // Protel DXP Scope 1 Expression Was: InDifferentialPair ('NewDifferentialPair2')
MatchedLengths DiffPair_MatchedLengths_10 [All] p0 off: scope1count=1 scope1_0_kind=Board scope1_0_value=Board scope2count=1 scope2_0_kind=Board scope2_0_value=Board commentlength=82 tolerance=5 amplitude=200 gap=20 style=90-Degree // Protel DXP Scope 1 Expression Was: InDifferentialPair ('NewDifferentialPair2')
MatchedLengths DiffPair_MatchedLengths_11 [All] p0 off: scope1count=1 scope1_0_kind=Board scope1_0_value=Board scope2count=1 scope2_0_kind=Board scope2_0_value=Board commentlength=82 tolerance=5 amplitude=200 gap=20 style=90-Degree // Protel DXP Scope 1 Expression Was: InDifferentialPair ('NewDifferentialPair1')
MatchedLengths DiffPair_MatchedLengths_12 [All] p0 off: scope1count=1 scope1_0_kind=Board scope1_0_value=Board scope2count=1 scope2_0_kind=Board scope2_0_value=Board commentlength=70 tolerance=5 amplitude=200 gap=20 style=90-Degree // Protel DXP Scope 1 Expression Was: InDifferentialPairClass('DIIF')
MatchedLengths DiffPair_MatchedLengths [InDifferentialPair ('NewDifferentialPair3')] p1: tolerance=5 checknetsindiffpair=TRUE checkdiffpairvsdiffpair=FALSE checkxsignals=FALSE checkothers=FALSE
MatchedLengths DiffPair_MatchedLengths_1 [InDifferentialPair ('NewDifferentialPair2')] p2: tolerance=5 checknetsindiffpair=TRUE checkdiffpairvsdiffpair=FALSE checkxsignals=FALSE checkothers=FALSE
MatchedLengths DiffPair_MatchedLengths_2 [InDifferentialPair ('NewDifferentialPair1')] p3: tolerance=5 checknetsindiffpair=TRUE checkdiffpairvsdiffpair=FALSE checkxsignals=FALSE checkothers=FALSE
MatchedLengths DiffPair_MatchedLengths_3 [InDifferentialPair ('NewDifferentialPair8')] p4: tolerance=5 checknetsindiffpair=TRUE checkdiffpairvsdiffpair=FALSE checkxsignals=FALSE checkothers=FALSE
MatchedLengths DiffPair_MatchedLengths_4 [InDifferentialPair ('NewDifferentialPair7')] p5: tolerance=5 checknetsindiffpair=TRUE checkdiffpairvsdiffpair=FALSE checkxsignals=FALSE checkothers=FALSE
MatchedLengths DiffPair_MatchedLengths_5 [InDifferentialPair ('NewDifferentialPair6')] p6: tolerance=5 checknetsindiffpair=TRUE checkdiffpairvsdiffpair=FALSE checkxsignals=FALSE checkothers=FALSE
MatchedLengths DiffPair_MatchedLengths_6 [InDifferentialPair ('NewDifferentialPair5')] p7: tolerance=5 checknetsindiffpair=TRUE checkdiffpairvsdiffpair=FALSE checkxsignals=FALSE checkothers=FALSE
MatchedLengths DiffPair_MatchedLengths_7 [InDifferentialPair ('NewDifferentialPair3')] p8: tolerance=5 checknetsindiffpair=TRUE checkdiffpairvsdiffpair=FALSE checkxsignals=FALSE checkothers=FALSE
MatchedLengths DiffPair_MatchedLengths_8 [InDifferentialPair ('NewDifferentialPair4')] p9: tolerance=5 checknetsindiffpair=TRUE checkdiffpairvsdiffpair=FALSE checkxsignals=FALSE checkothers=FALSE
MatchedLengths DiffPair_MatchedLengths_9 [InDifferentialPair ('NewDifferentialPair2')] p10: tolerance=5 checknetsindiffpair=TRUE checkdiffpairvsdiffpair=FALSE checkxsignals=FALSE checkothers=FALSE
MatchedLengths DiffPair_MatchedLengths_10 [InDifferentialPair ('NewDifferentialPair2')] p11: tolerance=5 checknetsindiffpair=TRUE checkdiffpairvsdiffpair=FALSE checkxsignals=FALSE checkothers=FALSE
MatchedLengths DiffPair_MatchedLengths_11 [InDifferentialPair ('NewDifferentialPair1')] p12: tolerance=5 checknetsindiffpair=TRUE checkdiffpairvsdiffpair=FALSE checkxsignals=FALSE checkothers=FALSE
MatchedLengths DiffPair_MatchedLengths_12 [InDifferentialPairClass('DIIF')] p13: tolerance=5 checknetsindiffpair=TRUE checkdiffpairvsdiffpair=FALSE checkxsignals=FALSE checkothers=FALSE
MinimumAnnularRing MinimumAnnularRing_ThermalPadVias [All] p0 off: scope1count=1 scope1_0_kind=Board scope1_0_value=Board scope2count=1 scope2_0_kind=Board scope2_0_value=Board commentlength=63 minimumring=3.9 // Protel DXP Scope 1 Expression Was: IsVia and InAnyComponent
MinimumAnnularRing [All] p0: scope1count=1 scope1_0_kind=Board scope1_0_value=Board scope2count=1 scope2_0_kind=Board scope2_0_value=Board commentlength=0 minimumring=3.9
MinimumAnnularRing MinimumAnnularRing_ThermalPadVias [IsVia and InAnyComponent] p1: minimumring=3.9
MinimumAnnularRing [All] p2: minimumring=3.9
MinimumSolderMaskSliver MinimumSolderMaskSliver_Logo [All] p0: scope1count=1 scope1_0_kind=ComponentClass scope1_0_value=Logo scope2count=1 scope2_0_kind=ComponentClass scope2_0_value=Logo commentlength=0
MinimumSolderMaskSliver [All] p0: scope1count=1 scope1_0_kind=Board scope1_0_value=Board scope2count=1 scope2_0_kind=Board scope2_0_value=Board commentlength=0
MinimumSolderMaskSliver MinimumSolderMaskSliver_Logo [InComponentClass('Logo') vs InComponentClass('Logo')] p1: minsoldermaskwidth=0.7
MinimumSolderMaskSliver [All] p2: minsoldermaskwidth=4
NetAntennae [All] p0: scope1count=1 scope1_0_kind=Board scope1_0_value=Board scope2count=1 scope2_0_kind=Board scope2_0_value=Board commentlength=0
PasteMaskExpansion [All] p0: scope1count=1 scope1_0_kind=Board scope1_0_value=Board scope2count=1 scope2_0_kind=Board scope2_0_value=Board commentlength=0 expansion=0
PlaneClearance [All] p0: scope1count=1 scope1_0_kind=Board scope1_0_value=Board scope2count=1 scope2_0_kind=Board scope2_0_value=Board commentlength=0 clearance=20
PlaneConnect [All] p0: scope1count=1 scope1_0_kind=Board scope1_0_value=Board scope2count=1 scope2_0_kind=Board scope2_0_value=Board commentlength=0 planeconnectstyle=Relief reliefexpansion=10 reliefentries=4 reliefconductorwidth=10 reliefairgap=10
PlaneConnect [All] p1: planeconnectstyle=Relief reliefexpansion=10 reliefentries=4 reliefconductorwidth=10 reliefairgap=10
PolygonConnect [All] p0: scope1count=1 scope1_0_kind=Board scope1_0_value=Board scope2count=1 scope2_0_kind=Board scope2_0_value=Board commentlength=0 connectstyle=Direct reliefconductorwidth=10 reliefentries=4 polygonreliefangle="90 Angle"
PolygonConnect [All] p1: connectstyle=Direct reliefconductorwidth=10 reliefentries=4 polygonreliefangle="90 Angle" airgapwidth=10
RoomDefinition BGA1 [All] p0 off: scope1count=1 scope1_0_kind=Board scope1_0_value=Board scope2count=1 scope2_0_kind=Board scope2_0_value=Board commentlength=57 region_x1=23660000 region_y1=31370000 region_x2=36912838 region_y2=46780017 confinementstyle=ConfineIn // Protel DXP Scope 1 Expression Was: WithinRoom('BGA1')
RoomDefinition BGA1 [WithinRoom('BGA1')] p1: confinementstyle=ConfineIn formatcopy=TRUE lockcomponents=FALSE outline 830,2144 1999.28,2144 1999.28,1384.28 1921,1306 1921,1272 1663,1014 1415,1014 1414,1013 1414,840 1477,777 1477,693 1467,683 1435,683 1418,666 1362,666 1362,620 1345,603 1266,603 1256,613 1256,647 1224,679 1190,679 1177,692 1177,733 1084,826 904,826 839,891 839,1037 807,1069 729,1069 711,1051 681,1051 674,1058 674,1151 678,1155 808,1155 844,1191 844,1388 830,1402
RoutingCorners [All] p0: scope1count=1 scope1_0_kind=Board scope1_0_value=Board scope2count=1 scope2_0_kind=Board scope2_0_value=Board commentlength=0 cornerstyle=45-Degree minsetback=100 maxsetback=100
RoutingLayers [All] p0: scope1count=1 scope1_0_kind=Board scope1_0_value=Board scope2count=1 scope2_0_kind=Board scope2_0_value=Board commentlength=0 top layer=Automatic mid layer 1=Automatic mid layer 2=Automatic mid layer 3=Automatic mid layer 4=Automatic bottom layer=Automatic
RoutingPriority [All] p0: scope1count=1 scope1_0_kind=Board scope1_0_value=Board scope2count=1 scope2_0_kind=Board scope2_0_value=Board commentlength=0
RoutingTopology [All] p0: scope1count=1 scope1_0_kind=Board scope1_0_value=Board scope2count=1 scope2_0_kind=Board scope2_0_value=Board commentlength=0 topology=Shortest
RoutingVias ThermalPadVias [All] p0 off: scope1count=1 scope1_0_kind=Board scope1_0_value=Board scope2count=1 scope2_0_kind=Board scope2_0_value=Board commentlength=63 holewidth=7.87 width=19.68 viastyle="Through Hole" minholewidth=5 minwidth=13 maxholewidth=12.99 maxwidth=23.62 // Protel DXP Scope 1 Expression Was: IsVia and InAnyComponent
RoutingVias [All] p0: scope1count=1 scope1_0_kind=Board scope1_0_value=Board scope2count=1 scope2_0_kind=Board scope2_0_value=Board commentlength=0 holewidth=12.2 width=22.4 viastyle="Through Hole" minholewidth=5.9 minwidth=15.74 maxholewidth=20 maxwidth=40
RoutingVias ThermalPadVias [IsVia and InAnyComponent] p1: holewidth=7.87 width=19.68 viastyle="Through Hole" minholewidth=5 minwidth=13 maxholewidth=12.99 maxwidth=23.62
RoutingVias [All] p2: holewidth=12.2 width=22.4 viastyle="Through Hole" minholewidth=5.9 minwidth=15.74 maxholewidth=20 maxwidth=40
SMDToCorner [All] p0: scope1count=1 scope1_0_kind=Board scope1_0_value=Board scope2count=1 scope2_0_kind=Board scope2_0_value=Board commentlength=0 distance=25000
SMDToCorner [All] p1: distance=25000
ShortCircuit [All] p0: scope1count=1 scope1_0_kind=Board scope1_0_value=Board scope2count=1 scope2_0_kind=Board scope2_0_value=Board commentlength=0 allowed=FALSE
SilkToBoardRegionClearance [All] p0 off: scope1count=1 scope1_0_kind=Board scope1_0_value=Board scope2count=1 scope2_0_kind=Board scope2_0_value=Board commentlength=130 // Protel DXP Scope 1 Expression Was: Not ((IsComment or IsDesignator) And (Hide <> 'False')) and not InRegion(1000,500,4000,800)
SilkToBoardRegionClearance [Not ((IsComment or IsDesignator) And (Hide <> 'False')) and not InRegion(1000,500,4000,800)] p1:
SilkToSilkClearance [All] p0: scope1count=1 scope1_0_kind=Board scope1_0_value=Board scope2count=1 scope2_0_kind=Board scope2_0_value=Board commentlength=0
SilkToSilkClearance [All] p1: silktosilkclearance=3
SilkToSolderMaskClearance SilkscreenOverComponentPads [All] p0 off: scope1count=1 scope1_0_kind=Board scope1_0_value=Board scope2count=1 scope2_0_kind=Board scope2_0_value=Board commentlength=44 // Protel DXP Scope 1 Expression Was: IsPad
SilkToSolderMaskClearance SilkscreenOverComponentPads [IsPad] p1: minsilkscreentomaskgap=3 clearancetoexposedcopper=TRUE
SolderMaskExpansion [All] p0: scope1count=1 scope1_0_kind=Board scope1_0_value=Board scope2count=1 scope2_0_kind=Board scope2_0_value=Board commentlength=0 expansion=0
SolderMaskExpansion [All] p1: expansion=0
UnRoutedNet [All] p0: scope1count=1 scope1_0_kind=Board scope1_0_value=Board scope2count=1 scope2_0_kind=Board scope2_0_value=Board commentlength=0
UnpouredPolygon [All] p0: scope1count=1 scope1_0_kind=Board scope1_0_value=Board scope2count=1 scope2_0_kind=Board scope2_0_value=Board commentlength=0
Width "Width_1_Diff Pairs" [All] p0: scope1count=1 scope1_0_kind=NetClass scope1_0_value="Diff Pairs" scope2count=1 scope2_0_kind=Board scope2_0_value=Board commentlength=0 maxlimit=5.2 minlimit=4 preferedwidth=5.2
Width [All] p0: scope1count=1 scope1_0_kind=Board scope1_0_value=Board scope2count=1 scope2_0_kind=Board scope2_0_value=Board commentlength=0 maxlimit=100 minlimit=4 preferedwidth=6
Width "Width_1_Diff Pairs" [InNetClass('Diff Pairs')] p1: maxlimit=5.2 minlimit=4 preferedwidth=5.2
Width [All] p2: maxlimit=100 minlimit=4 preferedwidth=6
13 further rules are at their usual default settings.

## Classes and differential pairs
pad class "Mounting Holes PADS": Free-TH1 Free-TH2 Free-TH3 Free-TH4 Free-TH5 Free-TH6 Free-TH7 Free-TH8 Free-TH9
net class "Diff Pairs": NetJ1_28 NetJ1_30 NetJ1_34 NetJ1_36 NetJ1_40 NetJ1_42 NetJ1_46 NetJ1_48 RADAR_LVDS_0M RADAR_LVDS_0P RADAR_LVDS_1M RADAR_LVDS_1P RADAR_LVDS_CLKM RADAR_LVDS_CLKP RADAR_LVDS_FRCLKM RADAR_LVDS_FRCLKP
component class Logo: Logo1 Logo5
component class FiducialMark: FID1 FID2 FID3 FID4 FID5 FID6
component class Label: LBL1
component class PROC073A_Decoupling_caps: C1 C2 C3 C4 C5 C6 C7 C8 C9 C10 C11 C12 C13 C14 C15 C16 C17 C18 C19 C20 C21 C22 C23 C24 C25 C26 C27 C28 C29 C30 C64 L1 L2 L3 L7 R1
component class PROC073A_EVM_Hardware: "CAUTION HOT SURFACE1" FID1 FID2 FID3 FID4 FID5 FID6 LBL1 Logo1 Logo2 LOGO3 Logo4 Logo5 ZZ1 ZZ2 ZZ3 ZZ4 ZZ5
component class PROC073A_HD_Connector_60Pin: J1 J2 R4 R5 R6 R7 R8 R9 R10 R11 R12 R13 R15 R16 R17 R18 R19 R20 R21 R22 R23 R24 R26 R27 R28 R30 R31 R32 R33 R34 R35 R36 R37 R38 R39 R40 R41 R42 R52 R53 R58 R59 R60 R61 R62 R63 R64 R65 R66 R67 R124 R125 R126 R127 R128 R129 R130 R131 R132 R133 R134 R135 R136 R137 R140
component class PROC073A_IWR6843_Chip: C31 C32 C33 R72 R73 R74 R75 R76 R77 R150 R152 R153 R154 R155 R156 R169 TP2 TP3 TP4 TP5 TP6 TP7 U1 Y1
component class PROC073A_PMIC: C37 C38 C39 C40 C41 C42 C43 C44 C45 C46 C47 C48 C49 C50 C51 C52 C53 C54 C55 C56 C60 C61 C62 C66 C67 DS1 L4 L5 L6 Q1 R3 R68 R69 R70 R71 R78 R79 R80 R81 R82 R83 R84 R85 R86 R87 R88 R89 R90 R91 R92 R93 R95 R96 R97 R98 R99 R100 R102 R118 R119 R120 R121 R122 R123 R138 R141 R148 R149 R163 R164 R165 R166 R167 R168 R170 R171 U4 U5 U9
component class PROC073A_QSPI_Flash_section: C34 C35 R43 R44 R45 R46 R47 R48 R49 R50 R51 U2
component class PROC073A_Temp_Current_sensor: C36 C57 C58 C59 C63 C65 R2 R14 R25 R29 R54 R55 R56 R57 R94 R101 R103 R104 R105 R106 R107 R108 R109 R110 R111 R112 R113 R114 R115 R116 R117 R139 R142 R143 R144 R145 R146 R147 R151 R157 R158 R159 R160 R161 R162 U3 U6 U7 U8 U10 U11
net class "TX and RX": RX1 RX2 RX3 RX4 TX1 TX2 TX3
component class AssemblyNote: ZZ1 ZZ2 ZZ3 ZZ4 ZZ5
differential pair NewDifferentialPair8: +NetJ1_30 -NetJ1_28
differential pair NewDifferentialPair7: +NetJ1_36 -NetJ1_34
differential pair NewDifferentialPair6: +NetJ1_42 -NetJ1_40
differential pair NewDifferentialPair5: +NetJ1_48 -NetJ1_46
differential pair NewDifferentialPair4: +RADAR_LVDS_FRCLKM -RADAR_LVDS_FRCLKP
differential pair NewDifferentialPair3: +RADAR_LVDS_CLKM -RADAR_LVDS_CLKP
differential pair NewDifferentialPair2: +RADAR_LVDS_1M -RADAR_LVDS_1P
differential pair " ": +RADAR_LVDS_0M -RADAR_LVDS_0P

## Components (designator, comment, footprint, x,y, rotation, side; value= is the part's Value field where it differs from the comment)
C1 "CGA5L1X7R0J226M160AC" 1206_180 1840,835 r180 top
C2 "CGA5L1X7R0J226M160AC" 1206_180 610,1650 r0 bottom
C3 "CGA5L1X7R0J226M160AC" 1206_180 850,1325 r180 bottom
C4 "GCM155R71C224KE02D" 0402L 1374.59,1252 r270 top
C5 "GCM155R71C224KE02D" 0402L 1419.18,926.41 r180 top
C6 "GCM155R71C224KE02D" 0402L 1325,985 r180 bottom
C7 "GCM21BR71A106KE22L" 0805_HV 1495.59,1255 r180 bottom
C8 "GCM21BR71A106KE22L" 0805_HV 1495.59,1365 r180 bottom
C9 "GCM155R71C224KE02D" 0402L 1200,840 r90 bottom
C10 "GCM155R71C224KE02D" 0402L 960.59,1045 r180 bottom
C11 "GCM155R71C224KE02D" 0402L 1007.18,1231.41 r270 bottom
C12 "GCM155R71C224KE02D" 0402L 1181.59,1204 r180 bottom
C13 "GCM21BR71A106KE22L" 0805_HV 1183.59,1264 r180 bottom
C14 "GCM155R71C224KE02D" 0402L 1505.59,925 r180 top
C15 "GCM21BR71A106KE22L" 0805_HV 1615,920 r270 top
C16 "GCM155R71C224KE02D" 0402L 1163.59,695 r90 top
C17 "GCM188R70J225KE22D" 0603 800.59,1055 r0 top
C18 "GCM188R71C105KA64D" 0603 1436.78,851.41 r180 top
C19 "GCM155R71C224KE02D" 0402L 1049.18,1231.41 r270 bottom
C20 "GCM155R71C224KE02D" 0402L 1346.59,1325 r180 bottom
C21 "GCM155R71C224KE02D" 0402L 806.59,1006 r0 top
C22 "GCM188R71C105KA64D" 0603 1440.59,995 r180 top
C23 "GCM21BR71A106KE22L" 0805_HV 1030.59,1350 r90 bottom
C24 "GCM21BR71A106KE22L" 0805_HV 1345.59,1235 r180 bottom
C25 "GCM155R71C104KA55D" 0402L 875.59,785 r0 top
C26 "GCM155R71C104KA55D" 0402L 1134.5,771 r90 top
C27 "GCM188R70J225KE22D" 0603 810.59,835 r0 top
C28 "GCM155R71C224KE02D" 0402L 850.59,1140 r0 top
C29 "GCM155R71C224KE02D" 0402L 980.59,985 r270 bottom
C30 "GCM155R71E103KA37D" 0402L 1105,795 r270 bottom
C31 "C0603X7S1A104K030BC" 0201_033 1049.59,892 r90 bottom
C32 "GJM1555C1H4R7BB01D" 0402L 1435.59,745 r90 top
C33 "GJM1555C1H4R7BB01D" 0402L 1315.59,650 r180 top
C34 "CGA2B3X7R1H104K050BB" 0402L 335,1075 r0 top
C35 "GCM188R71C105KA64D" 0603 335,1175 r270 top
C36 "CGA2B3X7R1H104K050BB" 0402L 900,425 r90 bottom
C37 "CL21B106KOQNNNE" 0805_HV 1385,325 r180 top
C38 "0402YC104KAT2A" 0402 1355,210 r180 top
C39 "0402YC104KAT2A" 0402 633.74,420 r0 top
C40 "GCM21BD70J226ME36L" 0805 1450,120 r270 top
C41 "GCM21BD70J226ME36L" 0805 1535,120 r90 top
C42 "CL21B106KOQNNNE" 0805_HV1 843.74,330 r180 top
C43 "0402YC104KAT2A" 0402 868.74,225 r0 top
C44 "GCM21BD70J226ME36L" 0805_HV 498.74,385 r0 top
C45 "GCM21BR71A106KE22L" 0805_HV 588.74,80 r0 top
C46 "GCM21BD70J226ME36L" 0805 870,95 r180 bottom
C47 "GCM21BD70J226ME36L" 0805 838.74,125 r90 top
C48 "GRM155R71C103KA01D" 0402 705,205 r270 bottom
C49 "CL21B106KOQNNNE" 0805_HV1 833.74,445 r90 top
C50 "CL10B105KQ8NNNC" 0603 743.74,505 r270 top
C51 "GRM188R70J104KA01D" 0603 708.74,815 r90 top
C52 "GRM155R71C103KA01D" 0402 438.74,250 r270 top
C53 "0402YC104KAT2A" 0402 1205,165 r0 bottom
C54 "CGB2A1X6S0J105K033BC" 0402 1355,255 r0 top
C55 "CGB2A1X6S0J105K033BC" 0402 633.74,375 r180 top
C56 "CGB2A1X6S0J105K033BC" 0402 868.74,270 r180 top
C57 "CGA2B3X7R1H104K050BB" 0402L 1560,320 r90 top
C58 "CGA2B3X7R1H104K050BB" 0402L 635,1430 r90 bottom
C59 "CGA2B3X7R1H104K050BB" 0402L 830,430 r270 bottom
C60 "CGA2B3X7S2A102K050BB" 0402 933.74,695 r270 top
C61 "GRM219R61C226ME15L" 0805_HV 1143.74,505 r0 bottom
C62 "0402YC104KAT2A" 0402 1060,360 r0 bottom
C63 "CGA2B3X7R1H104K050BB" 0402L 898.74,888.19 r180 bottom
C64 "CGA5L1X7R0J226M160AC" 1206_180 510,1585 r270 top
C65 "CGA2B3X7R1H104K050BB" 0402L 475,1905 r0 bottom
C66 "0402YC104KAT2A" 0402 1050,315 r0 bottom
C67 "0402YC104KAT2A" 0402 1365,740 r270 bottom
"CAUTION HOT SURFACE1" "CAUTION HOT SURFACE" IEC_HotSurface_Small 603,1849 r0 top
DS1 "TLMY1000-GS08" TLMx1000_Yellow 325,1310 r180 top
FID1 "Fiducial" Fiducial10-20 288.68,1841.73 r90 top
FID2 "Fiducial" Fiducial10-20 323.74,90 r90 bottom
FID3 "Fiducial" Fiducial10-20 1505,100 r90 bottom
FID4 "Fiducial" Fiducial10-20 1895,95 r90 top
FID5 "Fiducial" Fiducial10-20 313,1840 r90 bottom
FID6 "Fiducial" Fiducial10-20 323.74,90 r90 top
J1 "QSH-030-01-L-D-A" Samtec_QSH-030-01-X-D-A 1708.74,580 r0 bottom
J2 "QSH-030-01-L-D-A" Samtec_QSH-030-01-X-D-A 417.24,580 r180 bottom
L1 "BLM18KG121TH1D" 0603 1730,921 r180 top
L2 "BLM18KG121TH1D" 0603 835.59,1506 r0 bottom
L3 "BLM18KG121TH1D" 0603 835,1410 r0 bottom
L4 "DFE252012PD-R47M" DFE252012P 1315,105 r270 top
L5 "DFE252012PD-R47M" DFE252012P 943.74,125 r270 top
L6 "DFE252012PD-1R0M" DFE252012P 938.74,410 r0 top
L7 "BLM18KG121TH1D" 0603 585,1450 r0 top
LBL1 "THT-14-423-10" Label_650x200 1251.71,1814.13 r180 bottom
Logo1 "Texas Instruments" TI_Stacked_Overlay_Small 1706.68,490.06 r0 top
Logo2 "CE Mark" CE_Mark_5mm 1453.41,1596.36 r180 bottom
LOGO3 "FCC disclaimer" FCC_disclaimer 951.04,1952.72 r180 bottom (schematic designator Logo3)
Logo4 "WEEE logo" WEEE_Minimum 389,1829 r0 top
Logo5 "Texas Instruments" TI_Symbol_Overlay_Small 1218,1610 r180 bottom
Q1 "BSS123" SOT-23 306,1415 r270 top
R1 "MCT06030Z0000ZP500" 0603 1355.59,1410 r0 bottom
R2 "CRCW040210K0FKED" 0402L 1728.74,95 r270 bottom
R3 "PMR18EZPFV2L00" 1206 605,555 r90 top
R4 "CRCW02010000Z0ED" 0201_Silk 1448.74,395 r180 bottom
R5 "CRCW02010000Z0ED" 0201_Silk 1448.74,290 r0 bottom
R6 "CRCW02010000Z0ED" 0201_Silk 1448.74,360 r180 bottom
R7 "CRCW02010000Z0ED" 0201_Silk 1575,405 r0 top
R8 "CRCW02010000Z0ED" 0201_Silk 1448.74,325 r180 bottom
R9 "CRCW02010000Z0ED" 0201_Silk 1448.74,430 r0 bottom
R10 "CRCW02010000Z0ED" 0201_Silk 1823.74,426.85 r180 top
R11 "CRCW02010000Z0ED" 0201_Silk 1575,440 r0 top
R12 "CRCW02010000Z0ED" 0201_Silk 1575,475 r180 top
R13 "CRCW02010000Z0ED" 0201_Silk 1943.74,445 r0 bottom
R14 "CRCW040210K0FKED" 0402L 1763.74,95 r270 bottom
R15 "CRCW020120R0FNED" 0201_033 1823.74,386.85 r0 top
R16 "CRCW02010000Z0ED" 0201_Silk 1945,515 r0 bottom
R17 "CRCW020120R0FNED" 0201_033 1823.74,346.85 r0 top
R18 "CRCW020120R0FNED" 0201_033 1575,510 r0 top
R19 "CRCW020120R0FNED" 0201_033 1448.74,465 r0 bottom
R20 "CRCW020120R0FNED" 0201_033 1448.74,500 r0 bottom
R21 "CRCW020120R0FNED" 0201_033 1705,600 r180 top
R22 "CRCW02010000Z0ED" 0201_Silk 1823.74,511.85 r180 top
R23 "CRCW020120R0FNED" 0201_033 1610,655 r0 top
R24 "CRCW02010000Z0ED" 0201_Silk 1823.74,546.85 r180 top
R25 "CRCW02010000Z0ED" 0201 1875,285 r0 top
R26 "CRCW020120R0FNED" 0201_033 1450,560 r0 bottom
R27 "CRCW020120R0FNED" 0201_033 1450,595 r0 bottom
R28 "CRCW020120R0FNED" 0201_033 1450,630 r0 bottom
R29 "CRCW02010000Z0ED" 0201 1875,250 r0 top
R30 "CRCW02010000Z0ED" 0201_Silk 1823.74,581.85 r180 top
R31 "CRCW02010000Z0ED" 0201_Silk 1943.74,480 r0 bottom
R32 "CRCW02010000Z0ED" 0201_Silk 1823.74,616.85 r180 top
R33 "CRCW02010000Z0ED" 0201_Silk 1823.74,651.85 r180 top
R34 "CRCW02010000Z0ED" 0201_Silk 1475,892 r0 bottom
R35 "CRCW02010000Z0ED" 0201_Silk 1823.74,686.85 r180 top
R36 "CRCW02010000Z0ED" 0201_Silk 1823.74,476.85 r180 top
R37 "CRCW02010000Z0ED" 0201_Silk 1515,926 r0 bottom
R38 "CRCW02010000Z0ED" 0201_Silk 1725,1050 r180 bottom
R39 "CRCW02010000Z0ED" 0201_Silk 1823.74,720 r180 top
R40 "CRCW02010000Z0ED" 0201_Silk 1725,1085 r180 bottom
R41 "CRCW02010000Z0ED" 0201_Silk 1823.74,755 r180 top
R42 "CRCW02010000Z0ED" 0201_Silk 1943.74,410 r180 bottom
R43 "ERJ-2GE0R00X" 0402 390,1190 r90 top
R44 "CRCW040210K0FKED" 0402L 480,715 r90 top
R45 "CRCW020133R2FNED" 0201_Silk 470,1090 r90 top
R46 "CRCW020133R2FNED" 0201_Silk 415,725 r90 top
R47 "CRCW020133R2FNED" 0201_Silk 518,725 r90 top
R48 "CRCW020133R2FNED" 0201_Silk 435,1090 r90 top
R49 "CRCW040210K0FKED" 0402L 435,1190 r90 top
R50 "CRCW040247K5FKED" 0402L 355,725 r90 top
R51 "CRCW020133R2FNED" 0201_Silk 395,1090 r90 top
R52 "CRCW040210K0FKED" 0402L 820,485 r0 bottom
R53 "CRCW040210K0FKED" 0402L 768.74,580 r90 bottom
R54 "CRCW040210K0FKED" 0402L 943.74,610 r90 bottom
R55 "CRCW02010000Z0ED" 0201 843.74,520 r0 bottom
R56 "CRCW02010000Z0ED" 0201 843.74,565 r0 bottom
R57 "CRCW04020000Z0ED" 0402 940,410 r270 bottom
R58 "CRCW02010000Z0ED" 0201_Silk 1950,715 r270 bottom
R59 "CRCW02010000Z0ED" 0201_Silk 1985,715 r270 bottom
R60 "CRCW02010000Z0ED" 0201_Silk 1450,670 r180 bottom
R61 "CRCW02010000Z0ED" 0201_Silk 1450,705 r180 bottom
R62 "CRCW02010000Z0ED" 0201_Silk 1450,740 r180 bottom
R63 "CRCW02010000Z0ED" 0201_Silk 1450,775 r180 bottom
R64 "CRCW02010000Z0ED" 0201_Silk 1475,858 r180 bottom
R65 "CRCW02010000Z0ED" 0201_Silk 1970,1030 r270 bottom
R66 "CRCW02010000Z0ED" 0201_Silk 1935,1030 r90 bottom
R67 "CRCW02010000Z0ED" 0201_Silk 1900,1030 r90 bottom
R68 "PMR18EZPFV2L00" 1206 450,555 r90 top
R69 "CRCW04020000Z0ED" 0402 1305,540 r270 bottom
R70 "PMR18EZPFV2L00" 1206 1720.83,90 r0 top
R71 "PMR18EZPFV2L00" 1206 495,1265 r180 bottom
R72 "ERJ-2GE0R00X" 0402 800.59,1420 r0 top
R73 "ERJ-2GE0R00X" 0402 800.59,1375 r0 top
R74 "ERJ-2GE0R00X" 0402 800.59,1285 r0 top
R75 "ERJ-2GE0R00X" 0402 800.59,1330 r0 top
R76 "ERJ-2GE0R00X" 0402 1490,740 r90 top
R77 "ERJ-2GE0R00X" 0402 1268.74,600 r180 top
R78 "ERJ-2GEJ511X" 0402L 430,1295 r270 top
R79 "ERJ-2GEJ511X" 0402L 305,1585 r270 bottom
R80 "CRCW0402100KFKED" 0402L 270,1585 r90 bottom
R81 "PMR18EZPFV2L00" 1206 730,205 r90 top
R82 "CRCW04020000Z0ED" 0402 1223.74,470 r0 top
R83 "CRCW04020000Z0ED" 0402 705,100 r270 bottom
R84 "CRCW04020000Z0ED" 0402 1113.74,470 r180 top
R85 "CRCW040212K1FKED" 0402 388.74,250 r90 top
R86 "CRCW040210K0JNED" 0402 1355,265 r0 bottom
R87 "CRCW040210K0JNED" 0402 929,515 r90 top
R88 "CRCW02010000Z0ED" 0201 1048.74,40 r0 top
R89 "CRCW02010000Z0ED" 0201 1048.74,75 r0 top
R90 "CRCW04020000Z0ED" 0402 1220,240 r270 bottom
R91 "CRCW04020000Z0ED" 0402 1020,240 r270 bottom
R92 "CRCW040248K7FKED" 0402 438.74,145 r90 top
R93 "CRCW04020000Z0ED" 0402 1208.23,344.49 r270 bottom
R94 "CRCW040210K0FKED" 0402L 1880,215 r180 top
R95 "CRCW040210K0JNED" 0402 1315,165 r180 bottom
R96 "PMR18EZPFV2L00" 1206 895,195 r180 bottom
R97 "CRCW040211K8FKED" 0402 1158.74,345 r90 bottom
R98 "CRCW04020000Z0ED" 0402 1005,520 r270 top
R99 "MCT06030Z0000ZP500" 0603 1025,640 r180 bottom
R100 "CRCW040210K0JNED" 0402 1060,160 r0 bottom
R101 "CRCW040210K0FKED" 0402L 1698.74,95 r90 bottom
R102 "CRCW04020000Z0ED" 0402 1312,60 r180 bottom
R103 "CRCW040210K0FKED" 0402L 1798.74,95 r90 bottom
R104 "CRCW040210K0FKED" 0402L 360,1480 r90 bottom
R105 "CRCW040210K0FKED" 0402L 325,1480 r90 bottom
R106 "CRCW040210K0FKED" 0402L 595,80 r270 bottom
R107 "CRCW040210K0FKED" 0402L 630,85 r270 bottom
R108 "CRCW02010000Z0ED" 0201 450,1525 r90 bottom
R109 "CRCW02010000Z0ED" 0201 715,490 r0 bottom
R110 "CRCW02010000Z0ED" 0201 485,1525 r90 bottom
R111 "CRCW02010000Z0ED" 0201 715,455 r0 bottom
R112 "CRCW040210K0FKED" 0402L 415,1385 r270 top
R113 "CRCW040210K0FKED" 0402L 375,1580 r270 top
R114 "CRCW040210K0FKED" 0402L 275,1580 r270 top
R115 "CRCW040210K0FKED" 0402L 635,460 r270 bottom
R116 "CRCW040210K0FKED" 0402L 555,80 r90 bottom
R117 "CRCW040210K0FKED" 0402L 615,160 r270 bottom
R118 "CRCW040210K0JNED" 0402 1065,60 r0 bottom
R119 "CRCW0402510RJNED" 0402 738.74,675 r270 bottom
R120 "ERJ-2RKF1003X" 0402 848.74,610 r0 bottom
R121 "CRCW04020000Z0ED" 0402 1003.74,520 r270 bottom
R122 "RC0603JR-071KL" 0603 1290,378 r90 bottom
R123 "PMR18EZPFV2L00" 1206 903.74,740 r0 bottom
R124 "CRCW020120R0FNED" 0201_033 658.74,800 r180 bottom
R125 "CRCW020120R0FNED" 0201_033 658.74,765 r180 bottom
R126 "CRCW020120R0FNED" 0201_033 643.74,730 r180 bottom
R127 "CRCW020120R0FNED" 0201_033 643.74,695 r180 bottom
R128 "CRCW020120R0FNED" 0201_033 643.74,660 r180 bottom
R129 "CRCW020120R0FNED" 0201_033 643.74,630 r180 bottom
R130 "CRCW020120R0FNED" 0201_033 643.74,595 r180 bottom
R131 "CRCW02010000Z0ED" 0201_Silk 285,580 r0 top
R132 "CRCW020120R0FNED" 0201_033 643.74,560 r180 bottom
R133 "CRCW02010000Z0ED" 0201_Silk 285,615 r0 top
R134 "CRCW02010000Z0ED" 0201_Silk 285,545 r0 top
R135 "CRCW02010000Z0ED" 0201_Silk 285,510 r0 top
R136 "CRCW02010000Z0ED" 0201_Silk 285,475 r0 top
R137 "CRCW02010000Z0ED" 0201_Silk 285,440 r0 top
R138 "RCS06030000Z0EA" 0603 738.74,660 r90 top
R139 "CRCW040210K0FKED" 0402L 960,1195 r90 bottom
R140 "CRCW02010000Z0ED" 0201_Silk 658.74,835 r180 bottom
R141 "CRCW040210K0JNED" 0402 1170,60 r180 bottom
R142 "CRCW040210K0FKED" 0402L 965,1115 r0 bottom
R143 "CRCW02010000Z0ED" 0201 888.74,1195 r90 bottom
R144 "CRCW02010000Z0ED" 0201 833.74,1195 r90 bottom
R145 "CRCW040210K0FKED" 0402L 798.74,1195 r270 bottom
R146 "CRCW040210K0FKED" 0402L 925,1195 r270 bottom
R147 "CRCW040210K0FKED" 0402L 965,1080 r180 bottom
R148 "CRCW040210K0JNED" 0402 423.74,50 r0 bottom
R149 "CRCW02010000Z0ED" 0201 413.74,120 r180 bottom
R150 "CRCW040210K0JNED" 0402 1950,715 r90 top
R151 "CRCW04020000Z0ED" 0402 985,410 r270 bottom
R152 "CRCW040210K0FKED" 0402L 1940,410 r180 top
R153 "CRCW0402100KFKED" 0402L 1840,1080 r0 bottom
R154 "CRCW0402100KFKED" 0402L 1840,1045 r0 bottom
R155 "CRCW0402100KFKED" 0402L 1945,455 r180 top
R156 "CRCW0402100KFKED" 0402L 1230,755 r90 bottom
R157 "CRCW040210K0FKED" 0402L 475,1835 r180 bottom
R158 "CRCW040210K0FKED" 0402L 475,1865 r0 bottom
R159 "CRCW02010000Z0ED" 0201 465,1720 r270 bottom
R160 "CRCW02010000Z0ED" 0201 500,1720 r270 bottom
R161 "CRCW040210K0FKED" 0402L 870,1795 r0 bottom
R162 "CRCW040210K0FKED" 0402L 870,1760 r180 bottom
R163 "CRCW040210K0JNED" 0402 638.7,249.69 r90 bottom
R164 "CRCW040210K0JNED" 0402 530,505 r90 top
R165 "CRCW04020000Z0ED" 0402 1120,600 r270 bottom
R166 "CRCW04020000Z0ED" 0402 1315,740 r270 bottom
R167 "CRCW04020000Z0ED" 0402 1126,270 r180 bottom
R168 "CRCW04020000Z0ED" 0402 1315,115 r0 bottom
R169 "CRCW040210K0JNED" 0402 1900,970 r180 top
R170 "CRCW040210K0JNED" 0402 1215,610 r0 bottom
R171 "CRCW04020000Z0ED" 0402 1245,520 r90 bottom
TP2 "TP_SM_1MM" TP_SM_1MM 385,345 r90 top
TP3 "TP_SM_1MM" TP_SM_1MM 545,1345 r90 top
TP4 "TP_SM_1MM" TP_SM_1MM 532,1277 r90 top
TP5 "TP_SM_1MM" TP_SM_1MM 691,1325 r90 top
TP6 "TP_SM_1MM" TP_SM_1MM 1552,760 r90 top
TP7 "TP_SM_1MM" TP_SM_1MM 1450,665 r90 top
U1 "IWR6843QAGABL" ABL0161B 1125.98,1059.62 r270 top
U2 "MX25V1635FZNQ" WSON-8L_6x5MM_EP 434,900 r90 top
U3 "TMP112AQDRLRQ1" DRL0006A 923.74,520 r270 bottom
U4 "LP87702DRHBRQ1" RHB0032N 1113.74,250 r270 top
U5 "TPS7A5301QRGRRQ1" RGR0020A 573.74,230 r0 top
U6 "INA226AIDGST" DGS0010A_L 1703.74,275 r180 top
U7 "INA226AIDGST" DGS0010A_L 495,1390 r0 bottom
U8 "INA226AIDGST" DGS0010A_L 795,325 r0 bottom
U9 "TPS22917DBVR" DBV0006A_N 838.74,660 r90 top
U10 "INA226AIDGST" DGS0010A_L 810.59,1020 r270 bottom
U11 "CAT24C08WI-GT3" SOIC-8 675,1820 r180 bottom
Y1 "CX3225SA40000D0PTWCC" Kyocera_CX3225SA 1335.59,735 r90 top
ZZ1 "This Assembly Note is for PCB labels only" AssemblyNoteLabel -833.57,3067.5 r0 top
ZZ2 "These assemblies are ESD sensitive, ESD precautions shall be observed." AssemblyNote -831.16,2990.34 r0 top
ZZ3 "These assemblies must be clean and free from flux and all contaminants. Use of no clean flux is not acceptable." AssemblyNote -831.16,2903.53 r0 top
ZZ4 "These assemblies must comply with workmanship standards IPC-A-610 Class 2, unless otherwise specified." AssemblyNote -835.98,2811.9 r0 top
ZZ5 "Refer SWRU545.pdf(section 2.3) for installing hardware" AssemblyNote -824,2697 r0 top

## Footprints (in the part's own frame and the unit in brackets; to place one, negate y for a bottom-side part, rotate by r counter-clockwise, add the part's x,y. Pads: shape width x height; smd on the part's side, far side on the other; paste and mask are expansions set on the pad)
0201 [mm] "Data from Kemet datasheet CC101_COM dated 7/28/11"
  rect 0.46x0.42 smd mask+0: 1(-0.33,0) 2(0.33,0)
0201_033 [mm] "SMD, 2-Leads, Height 0.33mm"
  rect 0.46x0.42 smd mask+0: 1(-0.33,0) 2(0.33,0)
0201_Silk [mm] "Data from Kemet datasheet CC101_COM dated 7/28/11"
  rect 0.46x0.42 smd mask+0: 1(-0.33,0) 2(0.33,0)
  silkscreen extent -0.75,-0.4 0.75,0.4
0402 [mm] "0402 from SM-752 data"
  rect 0.8x0.6 smd: 1(-0.6,0) 2(0.6,0)
  silkscreen extent -1.22,-0.52 1.22,0.52
0402L [mm] "0402 from SM-752 data"
  rect 0.6x0.5 smd: 1(-0.5,0) 2(0.5,0)
0603 [mm] "0603 from SM-752 data"
  rect 1x0.95 smd: 1(-0.8,0) 2(0.8,0)
  silkscreen extent -1.52,-0.69 1.52,0.69
0805 [mm] "0805 from SM-752 data"
  rect 1.3x1.5 smd: 1(-0.85,0) 2(0.85,0)
  silkscreen extent -1.72,-0.97 1.72,0.97
0805_HV [mil] "0805 with 30mil clearance between pads"
  rect 50x63 smd: 1(-40,0) 2(40,0)
  silkscreen extent -74,-40 74,40
0805_HV1 [mm] "Custom footprint based on analyzing multiple manufacturer recommendations"
  rrect10% 1x1.25 smd: 1(-1,0) 2(1,0)
  silkscreen extent -0.2,-0.75 0.2,0.75
1206 [mm] "1206 from SM-752 data"
  rect 1.3x1.85 smd: 1(-1.45,0) 2(1.45,0)
  silkscreen extent -2.4,-1.21 2.4,1.21
1206_180 [mm] "1206_180"
  rect 1.1x1.6 smd: 1(-1.7,0) 2(1.7,0)
  silkscreen extent -0.9,-1 0.9,1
